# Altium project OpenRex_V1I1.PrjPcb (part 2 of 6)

## Sheet [10] - CPU - GPIO, PWM, LEDS, BUTTONS.SchDoc
size A2; DocumentNumber: 10; SheetNumber: 10; SheetTotal: 31
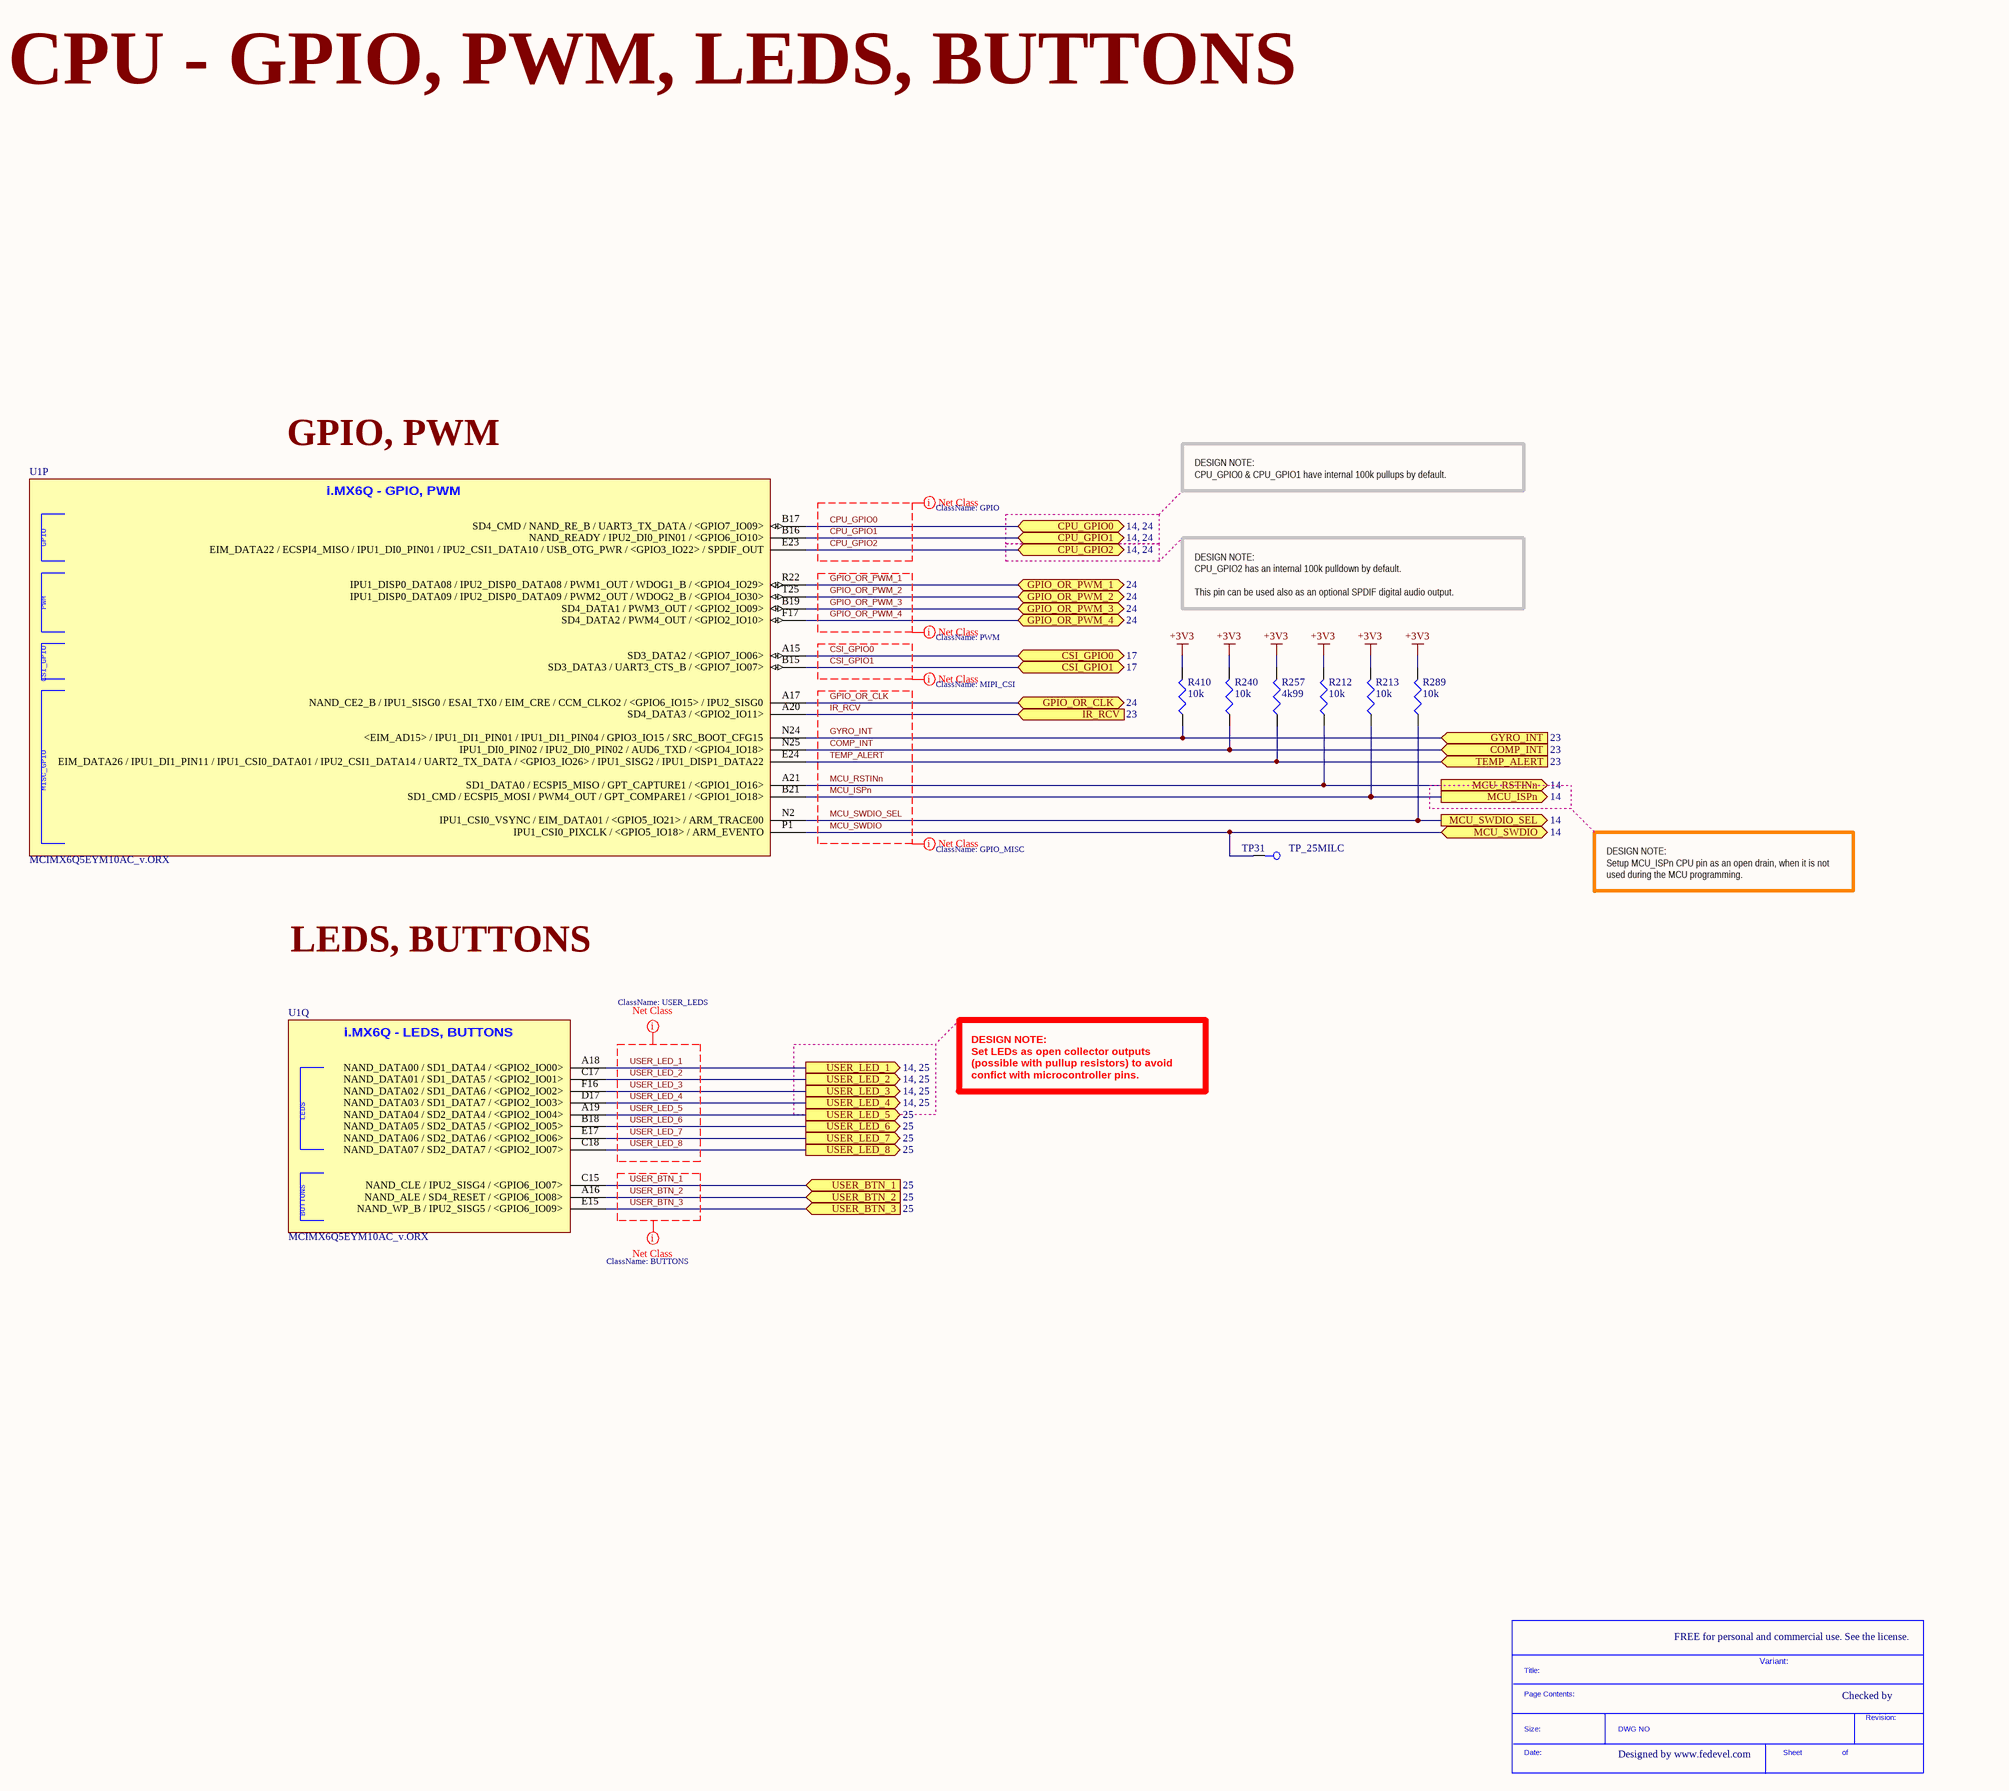
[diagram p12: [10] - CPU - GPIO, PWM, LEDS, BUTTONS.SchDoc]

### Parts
(Parts that share a designator on the sheet are numbered #1, #2 ... from top to bottom, then left to right.)
*#9  SDTitleBlock  (value not drawn)  (graphical)
R212  10k  [R0402]
R213  10k  [R0402]
R240  10k  [R0402]
R257  4k99  [R0402]
R289  10k  [R0402]
R410  10k  [R0402]
TP31  TP_25MILC  [TP_25C]  (no BOM)
U1  MCIMX6Q5EYM10AC_v.ORX  [PBGA624]  (parts P,Q of 21)

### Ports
COMP_INT (in, see 23), CPU_GPIO0 (bidir, see 14, 24), CPU_GPIO1 (bidir, see 14, 24), CPU_GPIO2 (bidir, see 14, 24), CSI_GPIO0 (bidir, see 17), CSI_GPIO1 (bidir, see 17), GPIO_OR_CLK (bidir, see 24), GPIO_OR_PWM_1 (bidir, see 24), GPIO_OR_PWM_2 (bidir, see 24), GPIO_OR_PWM_3 (bidir, see 24), GPIO_OR_PWM_4 (bidir, see 24), GYRO_INT (in, see 23), IR_RCV (in, see 23), MCU_ISPn (out, see 14), MCU_RSTINn (out, see 14), MCU_SWDIO (bidir, see 14), MCU_SWDIO_SEL (out, see 14), TEMP_ALERT (in, see 23), USER_BTN_1 (in, see 25), USER_BTN_2 (in, see 25), USER_BTN_3 (in, see 25), USER_LED_1 (out, see 14, 25), USER_LED_2 (out, see 14, 25), USER_LED_3 (out, see 14, 25), USER_LED_4 (out, see 14, 25), USER_LED_5 (out, see 25), USER_LED_6 (out, see 25), USER_LED_7 (out, see 25), USER_LED_8 (out, see 25)

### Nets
+3V3: R212.2 R213.2 R240.2 R257.2 R289.2 R410.2
COMP_INT: R240.1 U1.N25(IPU1_DI0_PIN02_/_IPU2_DI0_PIN02_/_AUD6_TXD_/_<GPIO4_IO18>) ; port COMP_INT
CPU_GPIO0: U1.B17(SD4_CMD_/_NAND_RE_B_/_UART3_TX_DATA_/_<GPIO7_IO09>) ; port CPU_GPIO0
CPU_GPIO1: U1.B16(NAND_READY_/_IPU2_DI0_PIN01_/_<GPIO6_IO10>) ; port CPU_GPIO1
CPU_GPIO2: U1.E23(EIM_DATA22_/_ECSPI4_MISO_/_IPU1_DI0_PIN01_/_IPU2_CSI1_DATA10_/_USB_OTG_PWR_/_<GPIO3_IO22>_/_SPDIF_OUT) ; port CPU_GPIO2
CSI_GPIO0: U1.A15(SD3_DATA2_/_<GPIO7_IO06>) ; port CSI_GPIO0
CSI_GPIO1: U1.B15(SD3_DATA3_/_UART3_CTS_B_/_<GPIO7_IO07>) ; port CSI_GPIO1
GPIO_OR_CLK: U1.A17(NAND_CE2_B_/_IPU1_SISG0_/_ESAI_TX0_/_EIM_CRE_/_CCM_CLKO2_/_<GPIO6_IO15>_/_IPU2_SISG0) ; port GPIO_OR_CLK
GPIO_OR_PWM_1: U1.R22(IPU1_DISP0_DATA08_/_IPU2_DISP0_DATA08_/_PWM1_OUT_/_WDOG1_B_/_<GPIO4_IO29>) ; port GPIO_OR_PWM_1
GPIO_OR_PWM_2: U1.T25(IPU1_DISP0_DATA09_/_IPU2_DISP0_DATA09_/_PWM2_OUT_/_WDOG2_B_/_<GPIO4_IO30>) ; port GPIO_OR_PWM_2
GPIO_OR_PWM_3: U1.B19(SD4_DATA1_/_PWM3_OUT_/_<GPIO2_IO09>) ; port GPIO_OR_PWM_3
GPIO_OR_PWM_4: U1.F17(SD4_DATA2_/_PWM4_OUT_/_<GPIO2_IO10>) ; port GPIO_OR_PWM_4
GYRO_INT: R410.1 U1.N24(<EIM_AD15>_/_IPU1_DI1_PIN01_/_IPU1_DI1_PIN04_/_GPIO3_IO15_/_SRC_BOOT_CFG15) ; port GYRO_INT
IR_RCV: U1.A20(SD4_DATA3_/_<GPIO2_IO11>) ; port IR_RCV
MCU_ISPn: R213.1 U1.B21(SD1_CMD_/_ECSPI5_MOSI_/_PWM4_OUT_/_GPT_COMPARE1_/_<GPIO1_IO18>) ; port MCU_ISPn
MCU_RSTINn: R212.1 U1.A21(SD1_DATA0_/_ECSPI5_MISO_/_GPT_CAPTURE1_/_<GPIO1_IO16>) ; port MCU_RSTINn
MCU_SWDIO: TP31.1 U1.P1(IPU1_CSI0_PIXCLK_/_<GPIO5_IO18>_/_ARM_EVENTO) ; port MCU_SWDIO
MCU_SWDIO_SEL: R289.1 U1.N2(IPU1_CSI0_VSYNC_/_EIM_DATA01_/_<GPIO5_IO21>_/_ARM_TRACE00) ; port MCU_SWDIO_SEL
TEMP_ALERT: R257.1 U1.E24(EIM_DATA26_/_IPU1_DI1_PIN11_/_IPU1_CSI0_DATA01_/_IPU2_CSI1_DATA14_/_UART2_TX_DATA_/_<GPIO3_IO26>_/_IPU1_SISG2_/_IPU1_DISP1_DATA22) ; port TEMP_ALERT
USER_BTN_1: U1.C15(NAND_CLE_/_IPU2_SISG4_/_<GPIO6_IO07>) ; port USER_BTN_1
USER_BTN_2: U1.A16(NAND_ALE_/_SD4_RESET_/_<GPIO6_IO08>) ; port USER_BTN_2
USER_BTN_3: U1.E15(NAND_WP_B_/_IPU2_SISG5_/_<GPIO6_IO09>) ; port USER_BTN_3
USER_LED_1: U1.A18(NAND_DATA00_/_SD1_DATA4_/_<GPIO2_IO00>) ; port USER_LED_1
USER_LED_2: U1.C17(NAND_DATA01_/_SD1_DATA5_/_<GPIO2_IO01>) ; port USER_LED_2
USER_LED_3: U1.F16(NAND_DATA02_/_SD1_DATA6_/_<GPIO2_IO02>) ; port USER_LED_3
USER_LED_4: U1.D17(NAND_DATA03_/_SD1_DATA7_/_<GPIO2_IO03>) ; port USER_LED_4
USER_LED_5: U1.A19(NAND_DATA04_/_SD2_DATA4_/_<GPIO2_IO04>) ; port USER_LED_5
USER_LED_6: U1.B18(NAND_DATA05_/_SD2_DATA5_/_<GPIO2_IO05>) ; port USER_LED_6
USER_LED_7: U1.E17(NAND_DATA06_/_SD2_DATA6_/_<GPIO2_IO06>) ; port USER_LED_7
USER_LED_8: U1.C18(NAND_DATA07_/_SD2_DATA7_/_<GPIO2_IO07>) ; port USER_LED_8

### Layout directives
net class PWM: GPIO_OR_PWM_1, GPIO_OR_PWM_2, GPIO_OR_PWM_3, GPIO_OR_PWM_4
net class GPIO: CPU_GPIO0, CPU_GPIO1, CPU_GPIO2
net class GPIO_MISC: COMP_INT, GPIO_OR_CLK, GYRO_INT, IR_RCV, MCU_ISPn, MCU_RSTINn, MCU_SWDIO, MCU_SWDIO_SEL, TEMP_ALERT
net class USER_LEDS: USER_LED_1, USER_LED_2, USER_LED_3, USER_LED_4, USER_LED_5, USER_LED_6, USER_LED_7, USER_LED_8
net class BUTTONS: USER_BTN_1, USER_BTN_2, USER_BTN_3
net class MIPI_CSI: CSI_GPIO0, CSI_GPIO1

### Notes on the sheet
- CPU - GPIO, PWM, LEDS, BUTTONS
- GPIO, PWM
- DESIGN NOTE:
  CPU_GPIO0 & CPU_GPIO1 have internal 100k pullups by default.
- DESIGN NOTE:
  CPU_GPIO2 has an internal 100k pulldown by default.
  This pin can be used also as an optional SPDIF digital audio output.
- DESIGN NOTE:
  Setup MCU_ISPn CPU pin as an open drain, when it is not used during the MCU programming.
- LEDS, BUTTONS
- DESIGN NOTE:
  Set LEDs as open collector outputs (possible with pullup resistors) to avoid confict with microcontroller pins.
- FREE for personal and commercial use. See the license.
- Variant:
- Checked by
- Designed by www.fedevel.com

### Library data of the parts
R212 R213 R240 R289 R410 = RC0402FR-0710KL: RES 10.0K OHM 1/16W 1% 0402 SMD; Manufacturer: Yageo; Power (Watts): 0.063W, 1/16W; .Checked PCB: used; Temperature Coefficient: ±100ppm/°C
R257 = RMCF0402FT4K99: RES TF 4.99K OHM 1% 1/16W 0402; Manufacturer: Stackpole Electronics Inc; Power (Watts): 0.063W, 1/16W; .Checked PCB: used; Temperature Coefficient: ±100ppm/°C
TP31 = TP_25MILC: Test Point 25mil
U1 = MCIMX6Q5EYM10AC_v.ORX: IC MCU 32BIT ARM QUAD 624FCBGA; Manufacturer: Freescale Semiconductor; Core Processor: ARM® Cortex™-A9; Core Size: 32-Bit Quad-Core; Speed: 1.0GHz; Connectivity: CAN, EBI/EMI, ESAI, Ethernet, GPMI, I2C, MMC/SD, PCI, SATA, SPI, UART, USB, USB OTG; Peripherals: DMA, HDMI, I2S/SSI/AC97, MIPI CSI, MIMI DSI, MIPI HIS, PWM, WDT; Number of I /O: 224; Program Memory Type: External Program Memory; RAM Size: 256K x 8; Voltage - Supply (Vcc/Vdd): 0.925 V ~ 1.5 V; Oscillator Type: Internal; .Creator: MM; .Checked PCB: MM, checked by RF

## Sheet [09] - CPU - SD, AUDIO, I2C, CAN.SchDoc
size A2; DocumentNumber: 9; SheetNumber: 9; SheetTotal: 31
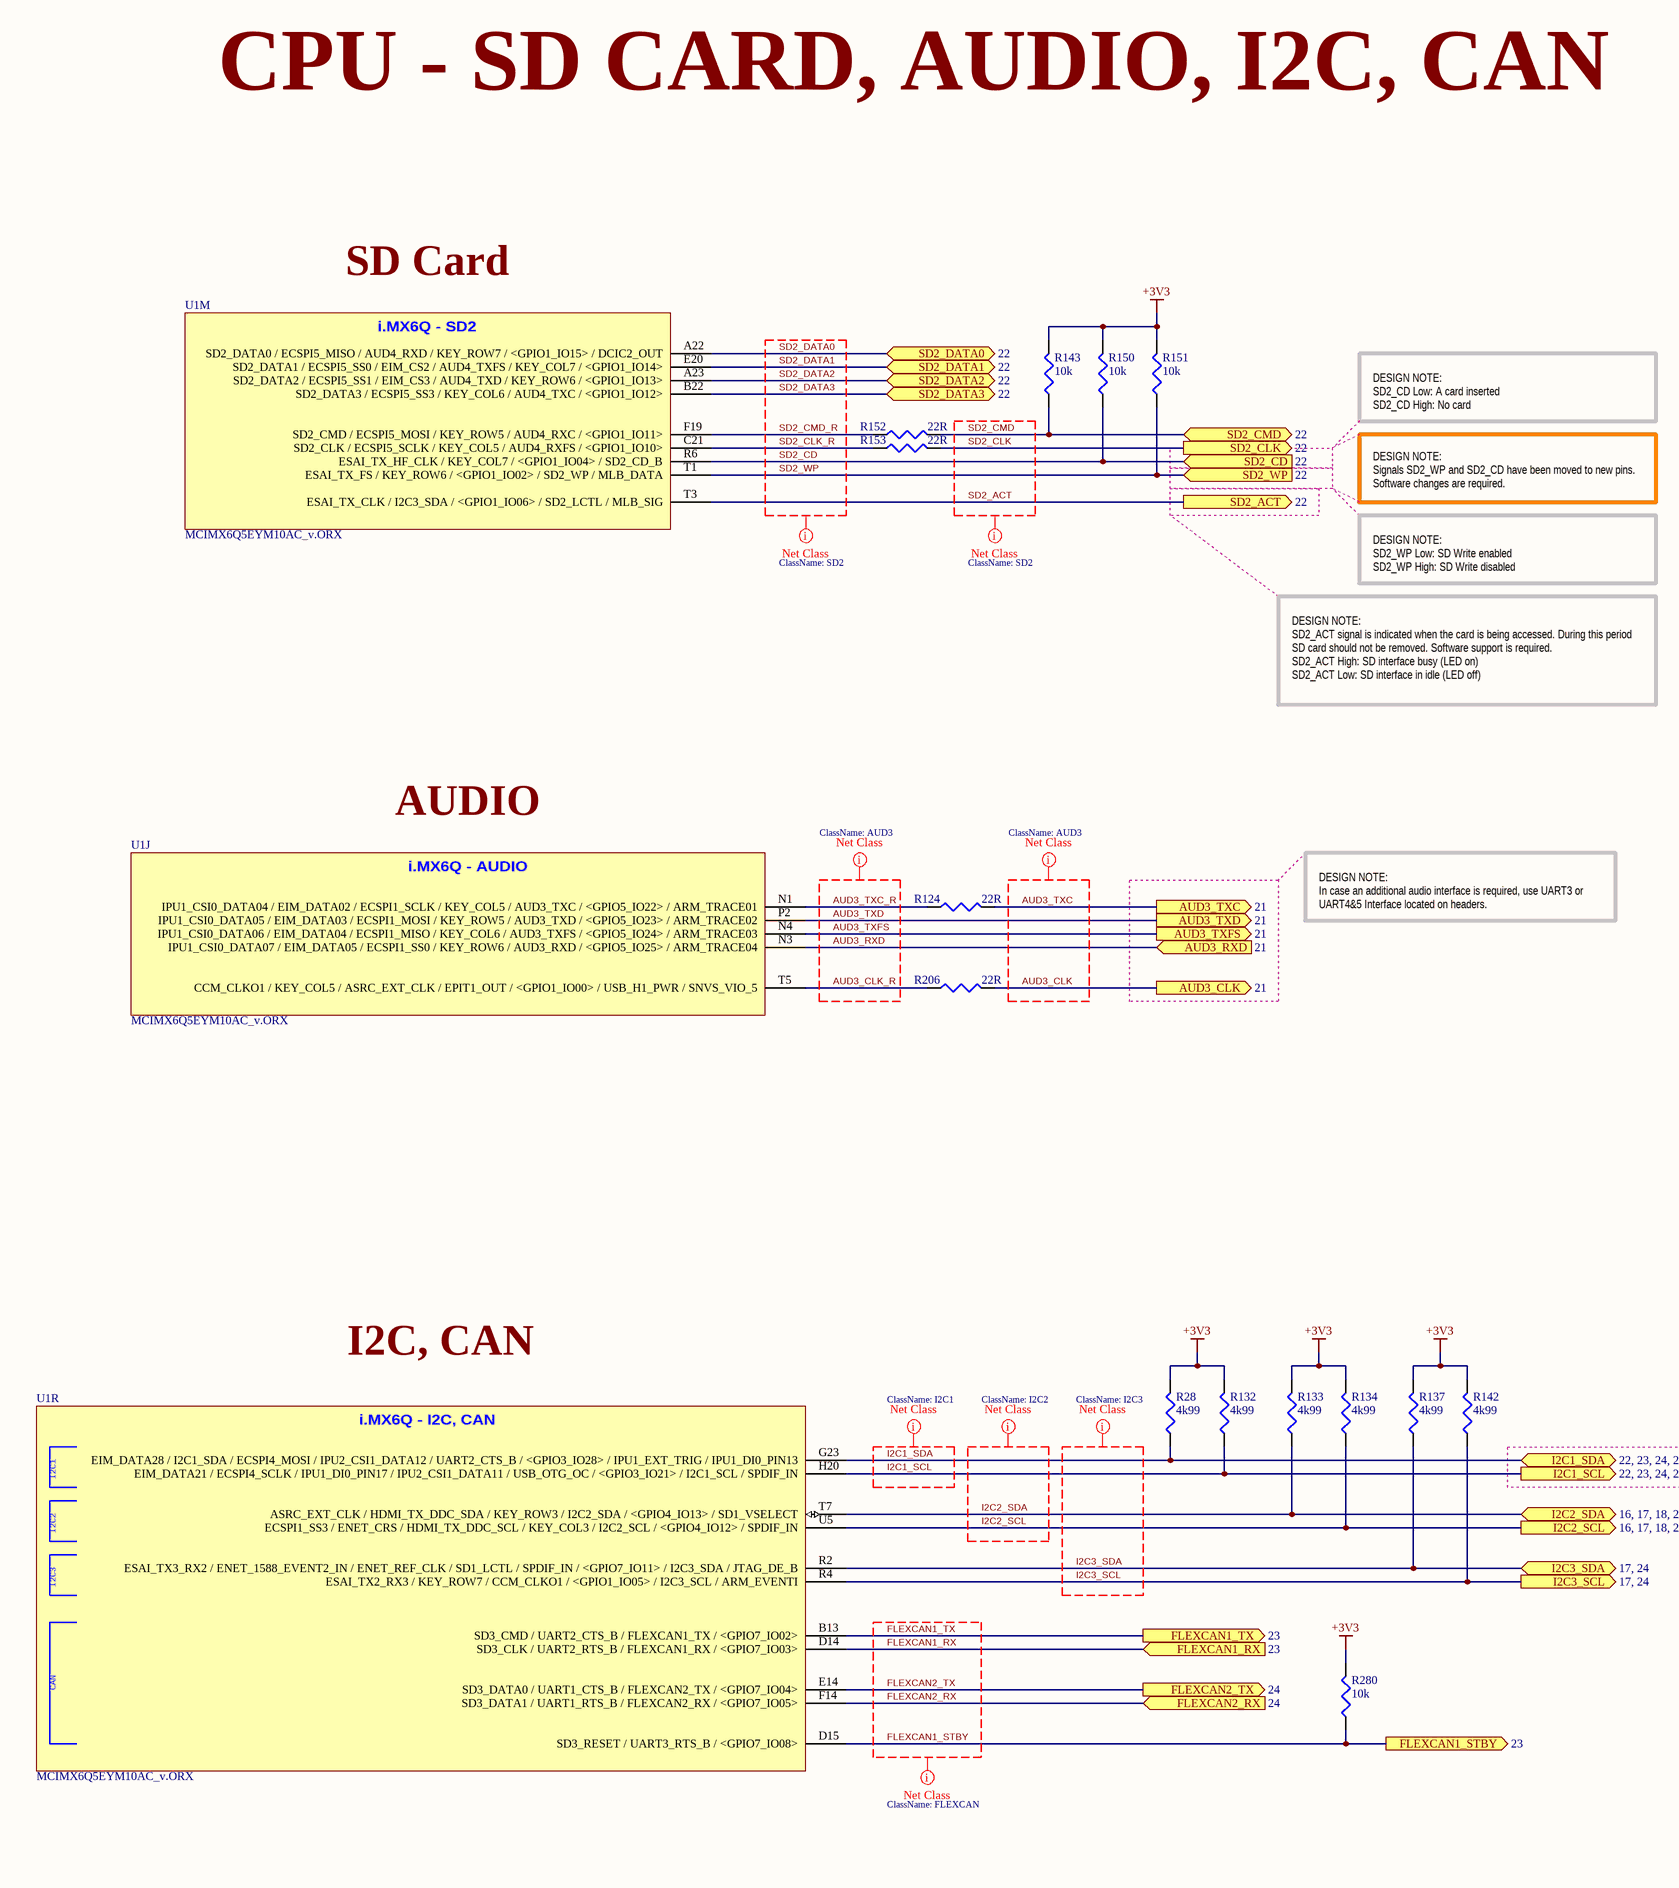
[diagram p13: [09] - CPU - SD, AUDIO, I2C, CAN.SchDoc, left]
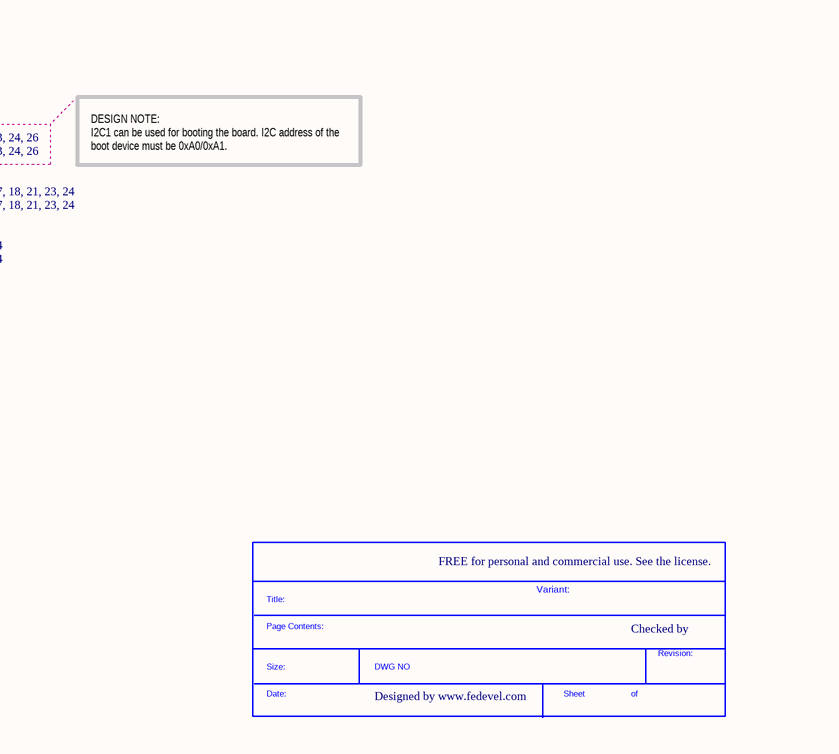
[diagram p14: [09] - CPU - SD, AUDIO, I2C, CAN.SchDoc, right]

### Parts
(Parts that share a designator on the sheet are numbered #1, #2 ... from top to bottom, then left to right.)
*#10  SDTitleBlock  (value not drawn)  (graphical)
R28  4k99  [R0402]
R124  22R  [R0402]
R132  4k99  [R0402]
R133  4k99  [R0402]
R134  4k99  [R0402]
R137  4k99  [R0402]
R142  4k99  [R0402]
R143  10k  [R0402]
R150  10k  [R0402]
R151  10k  [R0402]
R152  22R  [R0402]
R153  22R  [R0402]
R206  22R  [R0402]
R280  10k  [R0402]
U1  MCIMX6Q5EYM10AC_v.ORX  [PBGA624]  (parts J,M,R of 21)

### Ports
AUD3_CLK (out, see 21), AUD3_RXD (in, see 21), AUD3_TXC (out, see 21), AUD3_TXD (out, see 21), AUD3_TXFS (out, see 21), FLEXCAN1_RX (in, see 23), FLEXCAN1_STBY (out, see 23), FLEXCAN1_TX (out, see 23), FLEXCAN2_RX (in, see 24), FLEXCAN2_TX (out, see 24), I2C1_SCL (see 22, 23, 24, 26), I2C1_SDA (bidir, see 22, 23, 24, 26), I2C2_SCL (see 16, 17, 18, 21, 23, 24), I2C2_SDA (bidir, see 16, 17, 18, 21, 23, 24), I2C3_SCL (see 17, 24), I2C3_SDA (bidir, see 17, 24), SD2_ACT (out, see 22), SD2_CD (in, see 22), SD2_CLK (out, see 22), SD2_CMD (bidir, see 22), SD2_DATA0 (bidir, see 22), SD2_DATA1 (bidir, see 22), SD2_DATA2 (bidir, see 22), SD2_DATA3 (bidir, see 22), SD2_WP (in, see 22)

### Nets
+3V3: R28.2 R132.2 R133.2 R134.2 R137.2 R142.2 R143.2 R150.2 R151.2 R280.2
AUD3_CLK: R206.2 ; port AUD3_CLK
AUD3_CLK_R: R206.1 U1.T5(CCM_CLKO1_/_KEY_COL5_/_ASRC_EXT_CLK_/_EPIT1_OUT_/_<GPIO1_IO00>_/_USB_H1_PWR_/_SNVS_VIO_5)
AUD3_RXD: U1.N3(IPU1_CSI0_DATA07_/_EIM_DATA05_/_ECSPI1_SS0_/_KEY_ROW6_/_AUD3_RXD_/_<GPIO5_IO25>_/_ARM_TRACE04) ; port AUD3_RXD
AUD3_TXC: R124.2 ; port AUD3_TXC
AUD3_TXC_R: R124.1 U1.N1(IPU1_CSI0_DATA04_/_EIM_DATA02_/_ECSPI1_SCLK_/_KEY_COL5_/_AUD3_TXC_/_<GPIO5_IO22>_/_ARM_TRACE01)
AUD3_TXD: U1.P2(IPU1_CSI0_DATA05_/_EIM_DATA03_/_ECSPI1_MOSI_/_KEY_ROW5_/_AUD3_TXD_/_<GPIO5_IO23>_/_ARM_TRACE02) ; port AUD3_TXD
AUD3_TXFS: U1.N4(IPU1_CSI0_DATA06_/_EIM_DATA04_/_ECSPI1_MISO_/_KEY_COL6_/_AUD3_TXFS_/_<GPIO5_IO24>_/_ARM_TRACE03) ; port AUD3_TXFS
FLEXCAN1_RX: U1.D14(SD3_CLK_/_UART2_RTS_B_/_FLEXCAN1_RX_/_<GPIO7_IO03>) ; port FLEXCAN1_RX
FLEXCAN1_STBY: R280.1 U1.D15(SD3_RESET_/_UART3_RTS_B_/_<GPIO7_IO08>) ; port FLEXCAN1_STBY
FLEXCAN1_TX: U1.B13(SD3_CMD_/_UART2_CTS_B_/_FLEXCAN1_TX_/_<GPIO7_IO02>) ; port FLEXCAN1_TX
FLEXCAN2_RX: U1.F14(SD3_DATA1_/_UART1_RTS_B_/_FLEXCAN2_RX_/_<GPIO7_IO05>) ; port FLEXCAN2_RX
FLEXCAN2_TX: U1.E14(SD3_DATA0_/_UART1_CTS_B_/_FLEXCAN2_TX_/_<GPIO7_IO04>) ; port FLEXCAN2_TX
I2C1_SCL: R132.1 U1.H20(EIM_DATA21_/_ECSPI4_SCLK_/_IPU1_DI0_PIN17_/_IPU2_CSI1_DATA11_/_USB_OTG_OC_/_<GPIO3_IO21>_/_I2C1_SCL_/_SPDIF_IN) ; port I2C1_SCL
I2C1_SDA: R28.1 U1.G23(EIM_DATA28_/_I2C1_SDA_/_ECSPI4_MOSI_/_IPU2_CSI1_DATA12_/_UART2_CTS_B_/_<GPIO3_IO28>_/_IPU1_EXT_TRIG_/_IPU1_DI0_PIN13) ; port I2C1_SDA
I2C2_SCL: R134.1 U1.U5(ECSPI1_SS3_/_ENET_CRS_/_HDMI_TX_DDC_SCL_/_KEY_COL3_/_I2C2_SCL_/_<GPIO4_IO12>_/_SPDIF_IN) ; port I2C2_SCL
I2C2_SDA: R133.1 U1.T7(ASRC_EXT_CLK_/_HDMI_TX_DDC_SDA_/_KEY_ROW3_/_I2C2_SDA_/_<GPIO4_IO13>_/_SD1_VSELECT) ; port I2C2_SDA
I2C3_SCL: R142.1 U1.R4(ESAI_TX2_RX3_/_KEY_ROW7_/_CCM_CLKO1_/_<GPIO1_IO05>_/_I2C3_SCL_/_ARM_EVENTI) ; port I2C3_SCL
I2C3_SDA: R137.1 U1.R2(ESAI_TX3_RX2_/_ENET_1588_EVENT2_IN_/_ENET_REF_CLK_/_SD1_LCTL_/_SPDIF_IN_/_<GPIO7_IO11>_/_I2C3_SDA_/_JTAG_DE_B) ; port I2C3_SDA
SD2_ACT: U1.T3(ESAI_TX_CLK_/_I2C3_SDA_/_<GPIO1_IO06>_/_SD2_LCTL_/_MLB_SIG) ; port SD2_ACT
SD2_CD: R150.1 U1.R6(ESAI_TX_HF_CLK_/_KEY_COL7_/_<GPIO1_IO04>_/_SD2_CD_B) ; port SD2_CD
SD2_CLK: R153.2 ; port SD2_CLK
SD2_CLK_R: R153.1 U1.C21(SD2_CLK_/_ECSPI5_SCLK_/_KEY_COL5_/_AUD4_RXFS_/_<GPIO1_IO10>)
SD2_CMD: R143.1 R152.2 ; port SD2_CMD
SD2_CMD_R: R152.1 U1.F19(SD2_CMD_/_ECSPI5_MOSI_/_KEY_ROW5_/_AUD4_RXC_/_<GPIO1_IO11>)
SD2_DATA0: U1.A22(SD2_DATA0_/_ECSPI5_MISO_/_AUD4_RXD_/_KEY_ROW7_/_<GPIO1_IO15>_/_DCIC2_OUT) ; port SD2_DATA0
SD2_DATA1: U1.E20(SD2_DATA1_/_ECSPI5_SS0_/_EIM_CS2_/_AUD4_TXFS_/_KEY_COL7_/_<GPIO1_IO14>) ; port SD2_DATA1
SD2_DATA2: U1.A23(SD2_DATA2_/_ECSPI5_SS1_/_EIM_CS3_/_AUD4_TXD_/_KEY_ROW6_/_<GPIO1_IO13>) ; port SD2_DATA2
SD2_DATA3: U1.B22(SD2_DATA3_/_ECSPI5_SS3_/_KEY_COL6_/_AUD4_TXC_/_<GPIO1_IO12>) ; port SD2_DATA3
SD2_WP: R151.1 U1.T1(ESAI_TX_FS_/_KEY_ROW6_/_<GPIO1_IO02>_/_SD2_WP_/_MLB_DATA) ; port SD2_WP

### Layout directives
net class AUD3: AUD3_CLK, AUD3_CLK_R, AUD3_RXD, AUD3_TXC, AUD3_TXC_R, AUD3_TXD, AUD3_TXFS
net class FLEXCAN: FLEXCAN1_RX, FLEXCAN1_STBY, FLEXCAN1_TX, FLEXCAN2_RX, FLEXCAN2_TX
net class I2C1: I2C1_SCL, I2C1_SDA
net class I2C2: I2C2_SCL, I2C2_SDA
net class I2C3: I2C3_SCL, I2C3_SDA
net class SD2: SD2_ACT, SD2_CD, SD2_CLK, SD2_CLK_R, SD2_CMD, SD2_CMD_R, SD2_DATA0, SD2_DATA1, SD2_DATA2, SD2_DATA3, SD2_WP

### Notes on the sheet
- CPU - SD CARD, AUDIO, I2C, CAN
- SD Card
- DESIGN NOTE:
  SD2_CD Low: A card inserted
  SD2_CD High: No card
- DESIGN NOTE:
  Signals SD2_WP and SD2_CD have been moved to new pins. Software changes are required.
- DESIGN NOTE:
  SD2_WP Low: SD Write enabled
  SD2_WP High: SD Write disabled
- DESIGN NOTE:
  SD2_ACT signal is indicated when the card is being accessed. During this period SD card should not be removed. Software support is required.
  SD2_ACT High: SD interface busy (LED on)
  SD2_ACT Low: SD interface in idle (LED off)
- AUDIO
- DESIGN NOTE:
  In case an additional audio interface is required, use UART3 or UART4&5 Interface located on headers.
- I2C, CAN
- DESIGN NOTE:
  I2C1 can be used for booting the board. I2C address of the boot device must be 0xA0/0xA1.
- FREE for personal and commercial use. See the license.
- Variant:
- Checked by
- Designed by www.fedevel.com

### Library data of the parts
R28 R132-R134 R137 R142 = RMCF0402FT4K99: as R257 on sheet [10] - CPU - GPIO, PWM, LEDS, BUTTONS
R124 R152 R153 R206 = RC0402FR-0722RL: RES 22.0 OHM 1/16W 1% 0402 SMD; Manufacturer: Yageo; Resistance (Ohms): 22; Power (Watts): 0.063W, 1/16W; .Checked PCB: used; Temperature Coefficient: ±100ppm/°C
R143 R150 R151 R280 = RC0402FR-0710KL: as R212 on sheet [10] - CPU - GPIO, PWM, LEDS, BUTTONS
U1 = MCIMX6Q5EYM10AC_v.ORX: as U1 on sheet [10] - CPU - GPIO, PWM, LEDS, BUTTONS

## Sheet [03] - CPU - DDR3, DDR3 MEM.SchDoc
size A2; DocumentNumber: 3; SheetNumber: 3; SheetTotal: 31
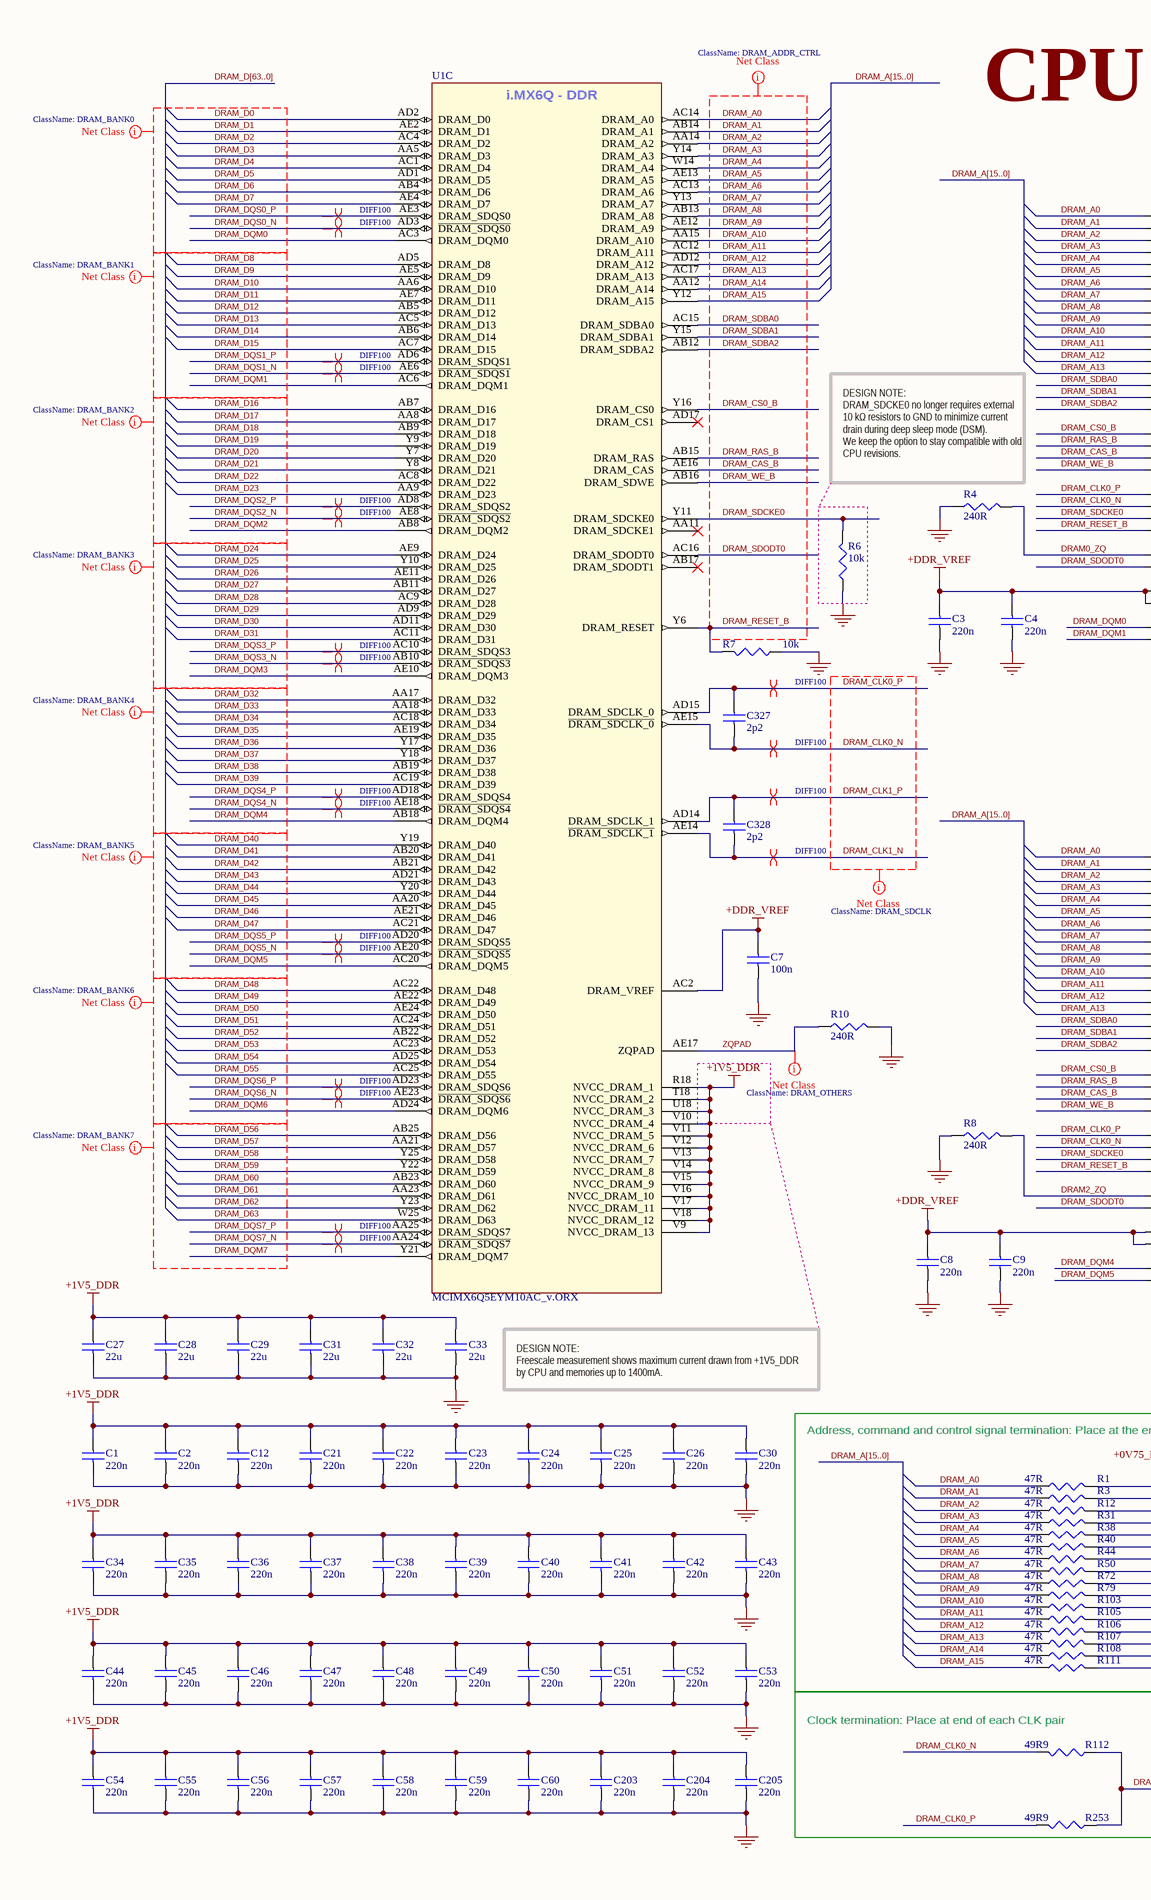
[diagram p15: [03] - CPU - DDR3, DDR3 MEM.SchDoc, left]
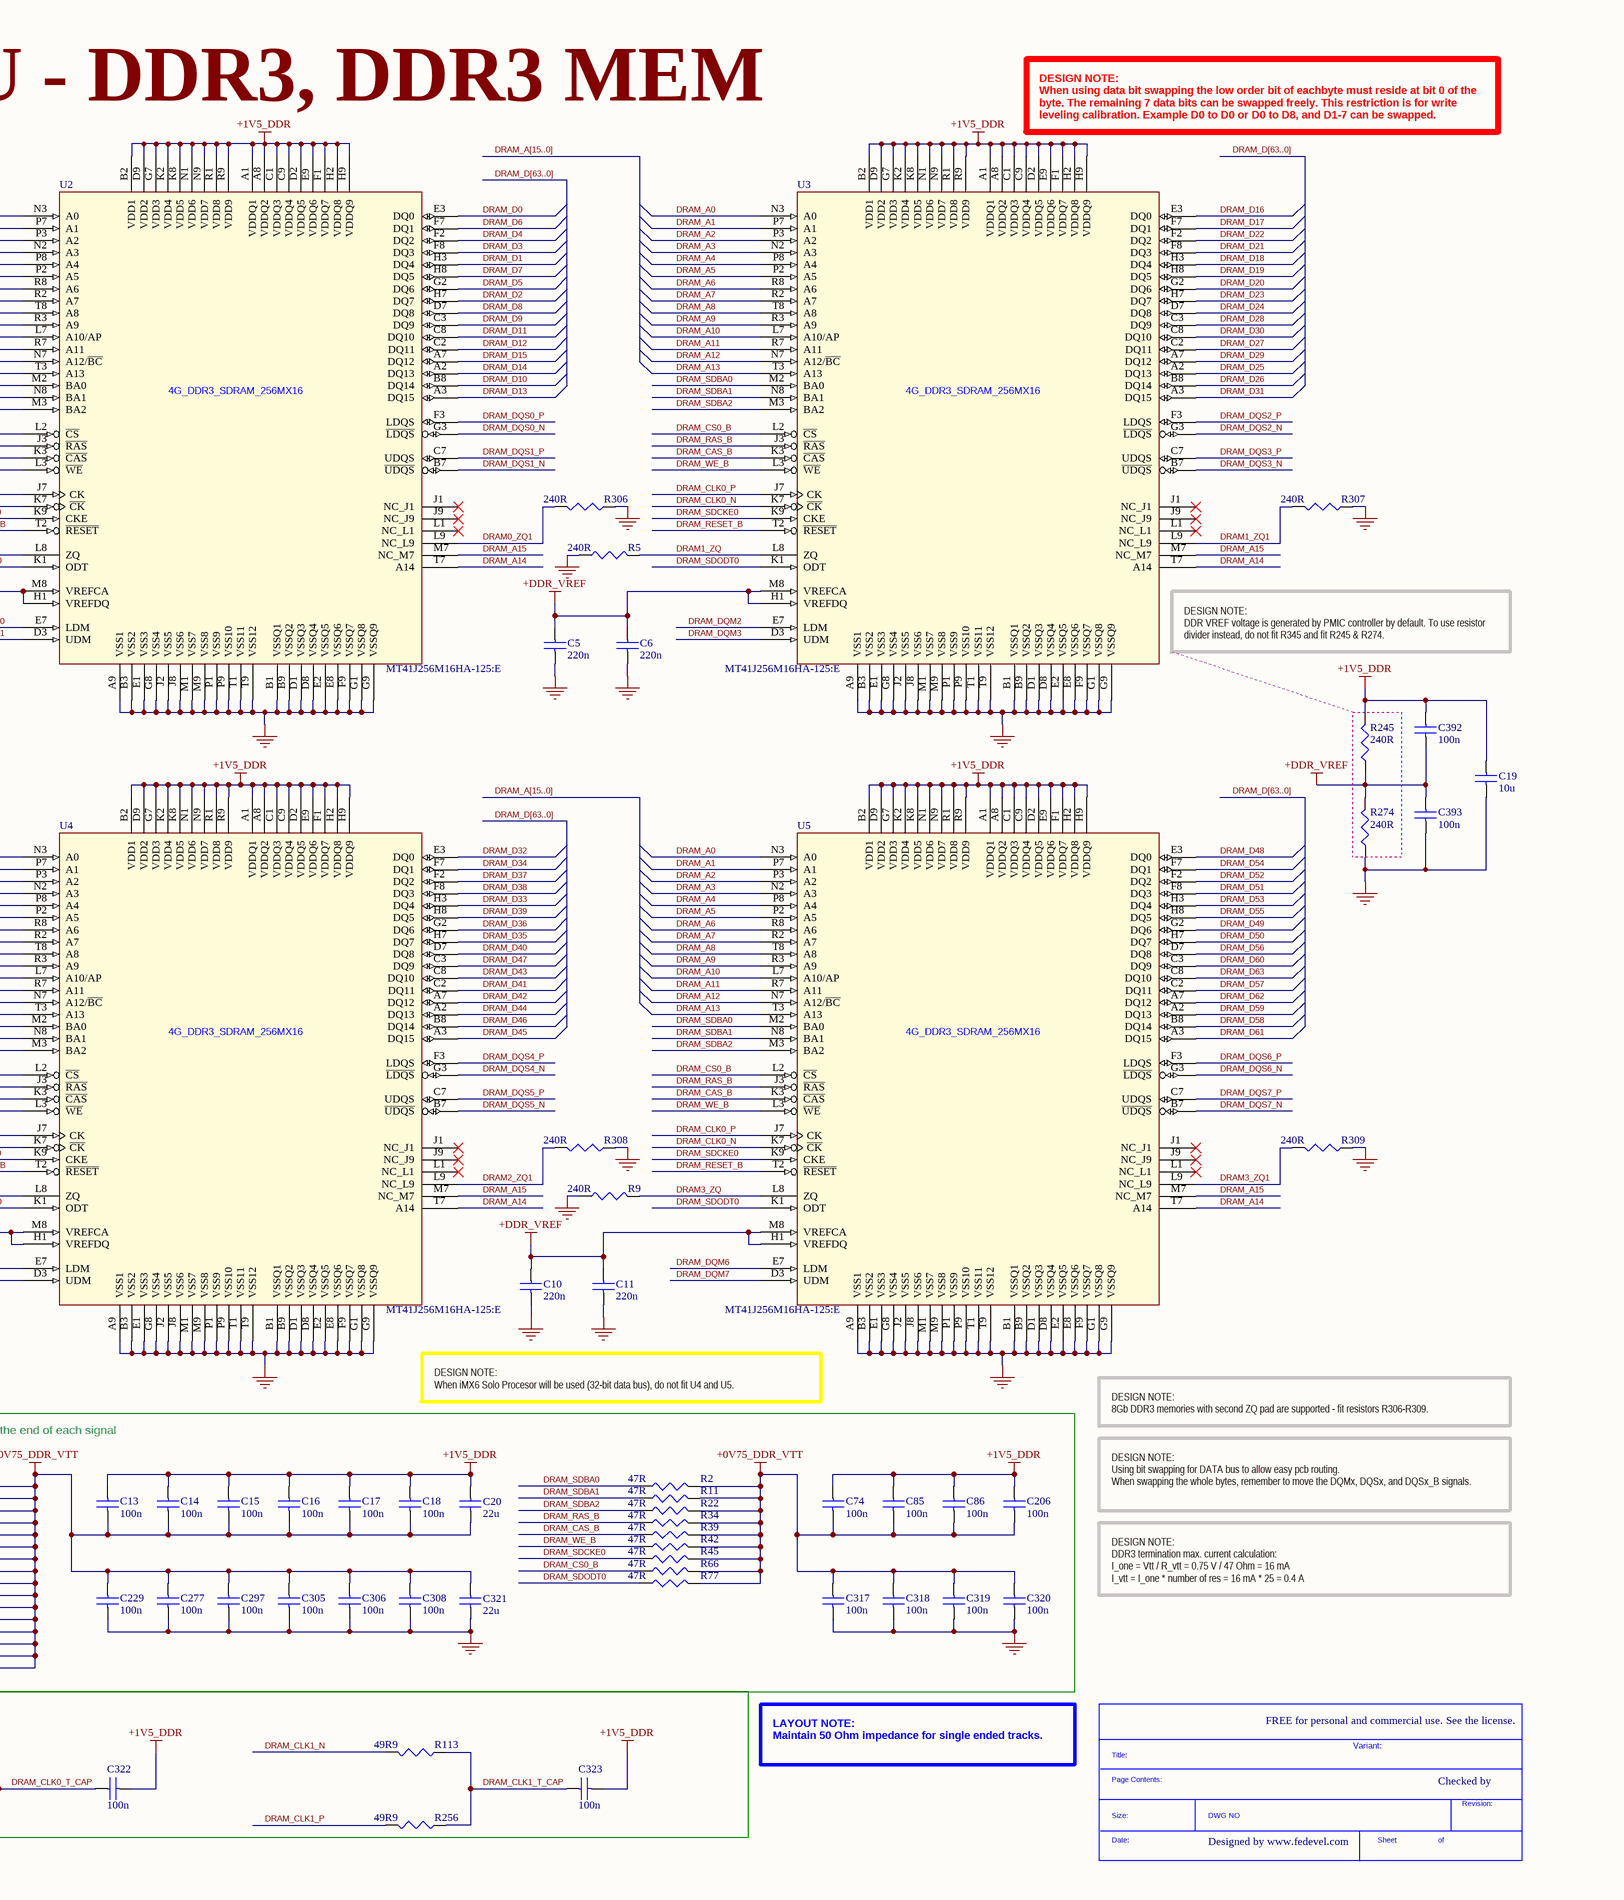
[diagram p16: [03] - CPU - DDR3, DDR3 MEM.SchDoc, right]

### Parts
(Parts that share a designator on the sheet are numbered #1, #2 ... from top to bottom, then left to right.)
*#11  SDTitleBlock  (value not drawn)  (graphical)
C1  220n  [C0201]
C2  220n  [C0201]
C3  220n  [C0201]
C4  220n  [C0201]
C5  220n  [C0201]
C6  220n  [C0201]
C7  100n  [C0201]
C8  220n  [C0201]
C9  220n  [C0201]
C10  220n  [C0201]
C11  220n  [C0201]
C12  220n  [C0201]
C13  100n  [C0201]
C14  100n  [C0201]
C15  100n  [C0201]
C16  100n  [C0201]
C17  100n  [C0201]
C18  100n  [C0201]
C19  10u  [C0603]
C20  22u  [C0603]
C21  220n  [C0201]
C22  220n  [C0201]
C23  220n  [C0201]
C24  220n  [C0201]
C25  220n  [C0201]
C26  220n  [C0201]
C27  22u  [C0603]
C28  22u  [C0603]
C29  22u  [C0603]
C30  220n  [C0201]
C31  22u  [C0603]
C32  22u  [C0603]
C33  22u  [C0603]
C34  220n  [C0201]
C35  220n  [C0201]
C36  220n  [C0201]
C37  220n  [C0201]
C38  220n  [C0201]
C39  220n  [C0201]
C40  220n  [C0201]
C41  220n  [C0201]
C42  220n  [C0201]
C43  220n  [C0201]
C44  220n  [C0201]
C45  220n  [C0201]
C46  220n  [C0201]
C47  220n  [C0201]
C48  220n  [C0201]
C49  220n  [C0201]
C50  220n  [C0201]
C51  220n  [C0201]
C52  220n  [C0201]
C53  220n  [C0201]
C54  220n  [C0201]
C55  220n  [C0201]
C56  220n  [C0201]
C57  220n  [C0201]
C58  220n  [C0201]
C59  220n  [C0201]
C60  220n  [C0201]
C74  100n  [C0201]
C85  100n  [C0201]
C86  100n  [C0201]
C203  220n  [C0201]
C204  220n  [C0201]
C205  220n  [C0201]
C206  100n  [C0201]
C229  100n  [C0201]
C277  100n  [C0201]
C297  100n  [C0201]
C305  100n  [C0201]
C306  100n  [C0201]
C308  100n  [C0201]
C317  100n  [C0201]
C318  100n  [C0201]
C319  100n  [C0201]
C320  100n  [C0201]
C321  22u  [C0603]
C322  100n  [C0201]
C323  100n  [C0201]
C327  2p2  [C0201]
C328  2p2  [C0201]
C392  100n  [C0402]
C393  100n  [C0402]
R1  47R  [R0201]
R2  47R  [R0201]
R3  47R  [R0201]
R4  240R  [R0201]
R5  240R  [R0201]
R6  10k  [R0201]
R7  10k  [R0201]
R8  240R  [R0201]
R9  240R  [R0201]
R10  240R  [R0201]
R11  47R  [R0201]
R12  47R  [R0201]
R22  47R  [R0201]
R31  47R  [R0201]
R34  47R  [R0201]
R38  47R  [R0201]
R39  47R  [R0201]
R40  47R  [R0201]
R42  47R  [R0201]
R44  47R  [R0201]
R45  47R  [R0201]
R50  47R  [R0201]
R66  47R  [R0201]
R72  47R  [R0201]
R77  47R  [R0201]
R79  47R  [R0201]
R103  47R  [R0201]
R105  47R  [R0201]
R106  47R  [R0201]
R107  47R  [R0201]
R108  47R  [R0201]
R111  47R  [R0201]
R112  49R9  [R0201]
R113  49R9  [R0201]
R245  240R  [R0402]
R253  49R9  [R0201]
R256  49R9  [R0201]
R274  240R  [R0402]
R306  240R  [R0201]
R307  240R  [R0201]
R308  240R  [R0201]
R309  240R  [R0201]
U1  MCIMX6Q5EYM10AC_v.ORX  [PBGA624]  (part C of 21)
U2  MT41J256M16HA-125:E  [96_FPGA_DD3_14mmx10mm-small_size]
U3  MT41J256M16HA-125:E  [96_FPGA_DD3_14mmx10mm-small_size]
U4  MT41J256M16HA-125:E  [96_FPGA_DD3_14mmx10mm-small_size]
U5  MT41J256M16HA-125:E  [96_FPGA_DD3_14mmx10mm-small_size]

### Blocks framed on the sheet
Clock termination: Place at end of each CLK pair: C322 C323 R112 R113 R253 R256

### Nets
+0V75_DDR_VTT: C13.2 C14.2 C15.2 C16.2 C17.2 C18.2 C20.2 C74.2 C85.2 C86.2 C206.2 C229.1 C277.1 C297.1 C305.1 C306.1 C308.1 C317.1 C318.1 C319.1 C320.1 C321.1 R1.2 R2.2 R3.2 R11.2 R12.2 R22.2 R31.2 R34.2 R38.2 R39.2 R40.2 R42.2 R44.2 R45.2 R50.2 R66.2 R72.2 R77.2 R79.2 R103.2 R105.2 R106.2 R107.2 R108.2 R111.2
+1V5_DDR: C1.1 C2.1 C12.1 C13.1 C14.1 C15.1 C16.1 C17.1 C18.1 C19.1 C20.1 C21.1 C22.1 C23.1 C24.1 C25.1 C26.1 C27.1 C28.1 C29.1 C30.1 C31.1 C32.1 C33.1 C34.1 C35.1 C36.1 C37.1 C38.1 C39.1 C40.1 C41.1 C42.1 C43.1 C44.1 C45.1 C46.1 C47.1 C48.1 C49.1 C50.1 C51.1 C52.1 C53.1 C54.1 C55.1 C56.1 C57.1 C58.1 C59.1 C60.1 C74.1 C85.1 C86.1 C203.1 C204.1 C205.1 C206.1 C322.2 C323.2 C392.1 R245.2 U1.R18(NVCC_DRAM_1) U1.T18(NVCC_DRAM_2) U1.U18(NVCC_DRAM_3) U1.V9(NVCC_DRAM_13) U1.V10(NVCC_DRAM_4) U1.V11(NVCC_DRAM_5) U1.V12(NVCC_DRAM_6) U1.V13(NVCC_DRAM_7) U1.V14(NVCC_DRAM_8) U1.V15(NVCC_DRAM_9) U1.V16(NVCC_DRAM_10) U1.V17(NVCC_DRAM_11) U1.V18(NVCC_DRAM_12) U2.A1(VDDQ1) U2.A8(VDDQ2) U2.B2(VDD1) U2.C1(VDDQ3) U2.C9(VDDQ4) U2.D2(VDDQ5) U2.D9(VDD2) U2.E9(VDDQ6) U2.F1(VDDQ7) U2.G7(VDD3) U2.H2(VDDQ8) U2.H9(VDDQ9) U2.K2(VDD4) U2.K8(VDD5) U2.N1(VDD6) U2.N9(VDD7) U2.R1(VDD8) U2.R9(VDD9) U3.A1(VDDQ1) U3.A8(VDDQ2) U3.B2(VDD1) U3.C1(VDDQ3) U3.C9(VDDQ4) U3.D2(VDDQ5) U3.D9(VDD2) U3.E9(VDDQ6) U3.F1(VDDQ7) U3.G7(VDD3) U3.H2(VDDQ8) U3.H9(VDDQ9) U3.K2(VDD4) U3.K8(VDD5) U3.N1(VDD6) U3.N9(VDD7) U3.R1(VDD8) U3.R9(VDD9) U4.A1(VDDQ1) U4.A8(VDDQ2) U4.B2(VDD1) U4.C1(VDDQ3) U4.C9(VDDQ4) U4.D2(VDDQ5) U4.D9(VDD2) U4.E9(VDDQ6) U4.F1(VDDQ7) U4.G7(VDD3) U4.H2(VDDQ8) U4.H9(VDDQ9) U4.K2(VDD4) U4.K8(VDD5) U4.N1(VDD6) U4.N9(VDD7) U4.R1(VDD8) U4.R9(VDD9) U5.A1(VDDQ1) U5.A8(VDDQ2) U5.B2(VDD1) U5.C1(VDDQ3) U5.C9(VDDQ4) U5.D2(VDDQ5) U5.D9(VDD2) U5.E9(VDDQ6) U5.F1(VDDQ7) U5.G7(VDD3) U5.H2(VDDQ8) U5.H9(VDDQ9) U5.K2(VDD4) U5.K8(VDD5) U5.N1(VDD6) U5.N9(VDD7) U5.R1(VDD8) U5.R9(VDD9)
+DDR_VREF: C3.1 C4.1 C5.1 C6.1 C7.1 C8.1 C9.1 C10.1 C11.1 C392.2 C393.1 R245.1 R274.2 U1.AC2(DRAM_VREF) U2.H1(VREFDQ) U2.M8(VREFCA) U3.H1(VREFDQ) U3.M8(VREFCA) U4.H1(VREFDQ) U4.M8(VREFCA) U5.H1(VREFDQ) U5.M8(VREFCA)
GND: C1.2 C2.2 C3.2 C4.2 C5.2 C6.2 C7.2 C8.2 C9.2 C10.2 C11.2 C12.2 C19.2 C21.2 C22.2 C23.2 C24.2 C25.2 C26.2 C27.2 C28.2 C29.2 C30.2 C31.2 C32.2 C33.2 C34.2 C35.2 C36.2 C37.2 C38.2 C39.2 C40.2 C41.2 C42.2 C43.2 C44.2 C45.2 C46.2 C47.2 C48.2 C49.2 C50.2 C51.2 C52.2 C53.2 C54.2 C55.2 C56.2 C57.2 C58.2 C59.2 C60.2 C203.2 C204.2 C205.2 C229.2 C277.2 C297.2 C305.2 C306.2 C308.2 C317.2 C318.2 C319.2 C320.2 C321.2 C393.2 R4.1 R5.1 R6.1 R7.1 R8.1 R9.1 R10.2 R274.1 R306.1 R307.1 R308.1 R309.1 U2.A9(VSS1) U2.B1(VSSQ1) U2.B3(VSS2) U2.B9(VSSQ2) U2.D1(VSSQ3) U2.D8(VSSQ4) U2.E1(VSS3) U2.E2(VSSQ5) U2.E8(VSSQ6) U2.F9(VSSQ7) U2.G1(VSSQ8) U2.G8(VSS4) U2.G9(VSSQ9) U2.J2(VSS5) U2.J8(VSS6) U2.M1(VSS7) U2.M9(VSS8) U2.P1(VSS9) U2.P9(VSS10) U2.T1(VSS11) U2.T9(VSS12) U3.A9(VSS1) U3.B1(VSSQ1) U3.B3(VSS2) U3.B9(VSSQ2) U3.D1(VSSQ3) U3.D8(VSSQ4) U3.E1(VSS3) U3.E2(VSSQ5) U3.E8(VSSQ6) U3.F9(VSSQ7) U3.G1(VSSQ8) U3.G8(VSS4) U3.G9(VSSQ9) U3.J2(VSS5) U3.J8(VSS6) U3.M1(VSS7) U3.M9(VSS8) U3.P1(VSS9) U3.P9(VSS10) U3.T1(VSS11) U3.T9(VSS12) U4.A9(VSS1) U4.B1(VSSQ1) U4.B3(VSS2) U4.B9(VSSQ2) U4.D1(VSSQ3) U4.D8(VSSQ4) U4.E1(VSS3) U4.E2(VSSQ5) U4.E8(VSSQ6) U4.F9(VSSQ7) U4.G1(VSSQ8) U4.G8(VSS4) U4.G9(VSSQ9) U4.J2(VSS5) U4.J8(VSS6) U4.M1(VSS7) U4.M9(VSS8) U4.P1(VSS9) U4.P9(VSS10) U4.T1(VSS11) U4.T9(VSS12) U5.A9(VSS1) U5.B1(VSSQ1) U5.B3(VSS2) U5.B9(VSSQ2) U5.D1(VSSQ3) U5.D8(VSSQ4) U5.E1(VSS3) U5.E2(VSSQ5) U5.E8(VSSQ6) U5.F9(VSSQ7) U5.G1(VSSQ8) U5.G8(VSS4) U5.G9(VSSQ9) U5.J2(VSS5) U5.J8(VSS6) U5.M1(VSS7) U5.M9(VSS8) U5.P1(VSS9) U5.P9(VSS10) U5.T1(VSS11) U5.T9(VSS12)
DRAM0_ZQ: R4.2 U2.L8(ZQ)
DRAM0_ZQ1: R306.2 U2.L9(NC_L9)
DRAM1_ZQ: R5.2 U3.L8(ZQ)
DRAM1_ZQ1: R307.2 U3.L9(NC_L9)
DRAM2_ZQ: R8.2 U4.L8(ZQ)
DRAM2_ZQ1: R308.2 U4.L9(NC_L9)
DRAM3_ZQ: R9.2 U5.L8(ZQ)
DRAM3_ZQ1: R309.2 U5.L9(NC_L9)
DRAM_A0: R1.1 U1.AC14(DRAM_A0) U2.N3(A0) U3.N3(A0) U4.N3(A0) U5.N3(A0)
DRAM_A1: R3.1 U1.AB14(DRAM_A1) U2.P7(A1) U3.P7(A1) U4.P7(A1) U5.P7(A1)
DRAM_A2: R12.1 U1.AA14(DRAM_A2) U2.P3(A2) U3.P3(A2) U4.P3(A2) U5.P3(A2)
DRAM_A3: R31.1 U1.Y14(DRAM_A3) U2.N2(A3) U3.N2(A3) U4.N2(A3) U5.N2(A3)
DRAM_A4: R38.1 U1.W14(DRAM_A4) U2.P8(A4) U3.P8(A4) U4.P8(A4) U5.P8(A4)
DRAM_A5: R40.1 U1.AE13(DRAM_A5) U2.P2(A5) U3.P2(A5) U4.P2(A5) U5.P2(A5)
DRAM_A6: R44.1 U1.AC13(DRAM_A6) U2.R8(A6) U3.R8(A6) U4.R8(A6) U5.R8(A6)
DRAM_A7: R50.1 U1.Y13(DRAM_A7) U2.R2(A7) U3.R2(A7) U4.R2(A7) U5.R2(A7)
DRAM_A8: R72.1 U1.AB13(DRAM_A8) U2.T8(A8) U3.T8(A8) U4.T8(A8) U5.T8(A8)
DRAM_A9: R79.1 U1.AE12(DRAM_A9) U2.R3(A9) U3.R3(A9) U4.R3(A9) U5.R3(A9)
DRAM_A10: R103.1 U1.AA15(DRAM_A10) U2.L7(A10/AP) U3.L7(A10/AP) U4.L7(A10/AP) U5.L7(A10/AP)
DRAM_A11: R105.1 U1.AC12(DRAM_A11) U2.R7(A11) U3.R7(A11) U4.R7(A11) U5.R7(A11)
DRAM_A12: R106.1 U1.AD12(DRAM_A12) U2.N7(A12/~{BC}) U3.N7(A12/~{BC}) U4.N7(A12/~{BC}) U5.N7(A12/~{BC})
DRAM_A13: R107.1 U1.AC17(DRAM_A13) U2.T3(A13) U3.T3(A13) U4.T3(A13) U5.T3(A13)
DRAM_A14: R108.1 U1.AA12(DRAM_A14) U2.T7(A14) U3.T7(A14) U4.T7(A14) U5.T7(A14)
DRAM_A15: R111.1 U1.Y12(DRAM_A15) U2.M7(NC_M7) U3.M7(NC_M7) U4.M7(NC_M7) U5.M7(NC_M7)
DRAM_CAS_B: R39.1 U1.AE16(DRAM_CAS) U2.K3(~{CAS}) U3.K3(~{CAS}) U4.K3(~{CAS}) U5.K3(~{CAS})
DRAM_CLK0_N: C327.2 R112.2 U1.AE15(~{DRAM_SDCLK_0}) U2.K7(~{CK}) U3.K7(~{CK}) U4.K7(~{CK}) U5.K7(~{CK})
DRAM_CLK0_P: C327.1 R253.2 U1.AD15(DRAM_SDCLK_0) U2.J7(CK) U3.J7(CK) U4.J7(CK) U5.J7(CK)
DRAM_CLK0_T_CAP: C322.1 R112.1 R253.1
DRAM_CLK1_N: C328.2 R113.2 U1.AE14(~{DRAM_SDCLK_1})
DRAM_CLK1_P: C328.1 R256.2 U1.AD14(DRAM_SDCLK_1)
DRAM_CLK1_T_CAP: C323.1 R113.1 R256.1
DRAM_CS0_B: R66.1 U1.Y16(DRAM_CS0) U2.L2(~{CS}) U3.L2(~{CS}) U4.L2(~{CS}) U5.L2(~{CS})
DRAM_D0: U1.AD2(DRAM_D0) U2.E3(DQ0)
DRAM_D1: U1.AE2(DRAM_D1) U2.H3(DQ4)
DRAM_D2: U1.AC4(DRAM_D2) U2.H7(DQ7)
DRAM_D3: U1.AA5(DRAM_D3) U2.F8(DQ3)
DRAM_D4: U1.AC1(DRAM_D4) U2.F2(DQ2)
DRAM_D5: U1.AD1(DRAM_D5) U2.G2(DQ6)
DRAM_D6: U1.AB4(DRAM_D6) U2.F7(DQ1)
DRAM_D7: U1.AE4(DRAM_D7) U2.H8(DQ5)
DRAM_D8: U1.AD5(DRAM_D8) U2.D7(DQ8)
DRAM_D9: U1.AE5(DRAM_D9) U2.C3(DQ9)
DRAM_D10: U1.AA6(DRAM_D10) U2.B8(DQ14)
DRAM_D11: U1.AE7(DRAM_D11) U2.C8(DQ10)
DRAM_D12: U1.AB5(DRAM_D12) U2.C2(DQ11)
DRAM_D13: U1.AC5(DRAM_D13) U2.A3(DQ15)
DRAM_D14: U1.AB6(DRAM_D14) U2.A2(DQ13)
DRAM_D15: U1.AC7(DRAM_D15) U2.A7(DQ12)
DRAM_D16: U1.AB7(DRAM_D16) U3.E3(DQ0)
DRAM_D17: U1.AA8(DRAM_D17) U3.F7(DQ1)
DRAM_D18: U1.AB9(DRAM_D18) U3.H3(DQ4)
DRAM_D19: U1.Y9(DRAM_D19) U3.H8(DQ5)
DRAM_D20: U1.Y7(DRAM_D20) U3.G2(DQ6)
DRAM_D21: U1.Y8(DRAM_D21) U3.F8(DQ3)
DRAM_D22: U1.AC8(DRAM_D22) U3.F2(DQ2)
DRAM_D23: U1.AA9(DRAM_D23) U3.H7(DQ7)
DRAM_D24: U1.AE9(DRAM_D24) U3.D7(DQ8)
DRAM_D25: U1.Y10(DRAM_D25) U3.A2(DQ13)
DRAM_D26: U1.AE11(DRAM_D26) U3.B8(DQ14)
DRAM_D27: U1.AB11(DRAM_D27) U3.C2(DQ11)
DRAM_D28: U1.AC9(DRAM_D28) U3.C3(DQ9)
DRAM_D29: U1.AD9(DRAM_D29) U3.A7(DQ12)
DRAM_D30: U1.AD11(DRAM_D30) U3.C8(DQ10)
DRAM_D31: U1.AC11(DRAM_D31) U3.A3(DQ15)
DRAM_D32: U1.AA17(DRAM_D32) U4.E3(DQ0)
DRAM_D33: U1.AA18(DRAM_D33) U4.H3(DQ4)
DRAM_D34: U1.AC18(DRAM_D34) U4.F7(DQ1)
DRAM_D35: U1.AE19(DRAM_D35) U4.H7(DQ7)
DRAM_D36: U1.Y17(DRAM_D36) U4.G2(DQ6)
DRAM_D37: U1.Y18(DRAM_D37) U4.F2(DQ2)
DRAM_D38: U1.AB19(DRAM_D38) U4.F8(DQ3)
DRAM_D39: U1.AC19(DRAM_D39) U4.H8(DQ5)
DRAM_D40: U1.Y19(DRAM_D40) U4.D7(DQ8)
DRAM_D41: U1.AB20(DRAM_D41) U4.C2(DQ11)
DRAM_D42: U1.AB21(DRAM_D42) U4.A7(DQ12)
DRAM_D43: U1.AD21(DRAM_D43) U4.C8(DQ10)
DRAM_D44: U1.Y20(DRAM_D44) U4.A2(DQ13)
DRAM_D45: U1.AA20(DRAM_D45) U4.A3(DQ15)
DRAM_D46: U1.AE21(DRAM_D46) U4.B8(DQ14)
DRAM_D47: U1.AC21(DRAM_D47) U4.C3(DQ9)
DRAM_D48: U1.AC22(DRAM_D48) U5.E3(DQ0)
DRAM_D49: U1.AE22(DRAM_D49) U5.G2(DQ6)
DRAM_D50: U1.AE24(DRAM_D50) U5.H7(DQ7)
DRAM_D51: U1.AC24(DRAM_D51) U5.F8(DQ3)
DRAM_D52: U1.AB22(DRAM_D52) U5.F2(DQ2)
DRAM_D53: U1.AC23(DRAM_D53) U5.H3(DQ4)
DRAM_D54: U1.AD25(DRAM_D54) U5.F7(DQ1)
DRAM_D55: U1.AC25(DRAM_D55) U5.H8(DQ5)
DRAM_D56: U1.AB25(DRAM_D56) U5.D7(DQ8)
DRAM_D57: U1.AA21(DRAM_D57) U5.C2(DQ11)
DRAM_D58: U1.Y25(DRAM_D58) U5.B8(DQ14)
DRAM_D59: U1.Y22(DRAM_D59) U5.A2(DQ13)
DRAM_D60: U1.AB23(DRAM_D60) U5.C3(DQ9)
DRAM_D61: U1.AA23(DRAM_D61) U5.A3(DQ15)
DRAM_D62: U1.Y23(DRAM_D62) U5.A7(DQ12)
DRAM_D63: U1.W25(DRAM_D63) U5.C8(DQ10)
DRAM_DQM0: U1.AC3(DRAM_DQM0) U2.E7(LDM)
DRAM_DQM1: U1.AC6(DRAM_DQM1) U2.D3(UDM)
DRAM_DQM2: U1.AB8(DRAM_DQM2) U3.E7(LDM)
DRAM_DQM3: U1.AE10(DRAM_DQM3) U3.D3(UDM)
DRAM_DQM4: U1.AB18(DRAM_DQM4) U4.E7(LDM)
DRAM_DQM5: U1.AC20(DRAM_DQM5) U4.D3(UDM)
DRAM_DQM6: U1.AD24(DRAM_DQM6) U5.E7(LDM)
DRAM_DQM7: U1.Y21(DRAM_DQM7) U5.D3(UDM)
DRAM_DQS0_N: U1.AD3(~{DRAM_SDQS0}) U2.G3(~{LDQS})
DRAM_DQS0_P: U1.AE3(DRAM_SDQS0) U2.F3(LDQS)
DRAM_DQS1_N: U1.AE6(~{DRAM_SDQS1}) U2.B7(~{UDQS})
DRAM_DQS1_P: U1.AD6(DRAM_SDQS1) U2.C7(UDQS)
DRAM_DQS2_N: U1.AE8(~{DRAM_SDQS2}) U3.G3(~{LDQS})
DRAM_DQS2_P: U1.AD8(DRAM_SDQS2) U3.F3(LDQS)
DRAM_DQS3_N: U1.AB10(~{DRAM_SDQS3}) U3.B7(~{UDQS})
DRAM_DQS3_P: U1.AC10(DRAM_SDQS3) U3.C7(UDQS)
DRAM_DQS4_N: U1.AE18(~{DRAM_SDQS4}) U4.G3(~{LDQS})
DRAM_DQS4_P: U1.AD18(DRAM_SDQS4) U4.F3(LDQS)
DRAM_DQS5_N: U1.AE20(~{DRAM_SDQS5}) U4.B7(~{UDQS})
DRAM_DQS5_P: U1.AD20(DRAM_SDQS5) U4.C7(UDQS)
DRAM_DQS6_N: U1.AE23(~{DRAM_SDQS6}) U5.G3(~{LDQS})
DRAM_DQS6_P: U1.AD23(DRAM_SDQS6) U5.F3(LDQS)
DRAM_DQS7_N: U1.AA24(~{DRAM_SDQS7}) U5.B7(~{UDQS})
DRAM_DQS7_P: U1.AA25(DRAM_SDQS7) U5.C7(UDQS)
DRAM_RAS_B: R34.1 U1.AB15(DRAM_RAS) U2.J3(~{RAS}) U3.J3(~{RAS}) U4.J3(~{RAS}) U5.J3(~{RAS})
DRAM_RESET_B: R7.2 U1.Y6(DRAM_RESET) U2.T2(~{RESET}) U3.T2(~{RESET}) U4.T2(~{RESET}) U5.T2(~{RESET})
DRAM_SDBA0: R2.1 U1.AC15(DRAM_SDBA0) U2.M2(BA0) U3.M2(BA0) U4.M2(BA0) U5.M2(BA0)
DRAM_SDBA1: R11.1 U1.Y15(DRAM_SDBA1) U2.N8(BA1) U3.N8(BA1) U4.N8(BA1) U5.N8(BA1)
DRAM_SDBA2: R22.1 U1.AB12(DRAM_SDBA2) U2.M3(BA2) U3.M3(BA2) U4.M3(BA2) U5.M3(BA2)
DRAM_SDCKE0: R6.2 R45.1 U1.Y11(DRAM_SDCKE0) U2.K9(CKE) U3.K9(CKE) U4.K9(CKE) U5.K9(CKE)
DRAM_SDODT0: R77.1 U1.AC16(DRAM_SDODT0) U2.K1(ODT) U3.K1(ODT) U4.K1(ODT) U5.K1(ODT)
DRAM_WE_B: R42.1 U1.AB16(DRAM_SDWE) U2.L3(~{WE}) U3.L3(~{WE}) U4.L3(~{WE}) U5.L3(~{WE})
ZQPAD: R10.1 U1.AE17(ZQPAD)

Not connected (* = marked no-connect by the designer): U1 AA11(DRAM_SDCKE1)* AB17(DRAM_SDODT1)* AD17(DRAM_CS1)*; U2 J1(NC_J1)* J9(NC_J9)* L1(NC_L1)*; U3 J1(NC_J1)* J9(NC_J9)* L1(NC_L1)*; U4 J1(NC_J1)* J9(NC_J9)* L1(NC_L1)*; U5 J1(NC_J1)* J9(NC_J9)* L1(NC_L1)*

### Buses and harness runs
bus DRAM_A[15..0]
bus DRAM_D[63..0]

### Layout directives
net class DRAM_BANK0: DRAM_D0, DRAM_D1, DRAM_D2, DRAM_D3, DRAM_D4, DRAM_D5, DRAM_D6, DRAM_D7, DRAM_DQM0, DRAM_DQS0_N, DRAM_DQS0_P
net class DRAM_BANK1: DRAM_D8, DRAM_D9, DRAM_D10, DRAM_D11, DRAM_D12, DRAM_D13, DRAM_D14, DRAM_D15, DRAM_DQM1, DRAM_DQS1_N, DRAM_DQS1_P
net class DRAM_BANK2: DRAM_D16, DRAM_D17, DRAM_D18, DRAM_D19, DRAM_D20, DRAM_D21, DRAM_D22, DRAM_D23, DRAM_DQM2, DRAM_DQS2_N, DRAM_DQS2_P
net class DRAM_BANK3: DRAM_D24, DRAM_D25, DRAM_D26, DRAM_D27, DRAM_D28, DRAM_D29, DRAM_D30, DRAM_D31, DRAM_DQM3, DRAM_DQS3_N, DRAM_DQS3_P
net class DRAM_BANK4: DRAM_D32, DRAM_D33, DRAM_D34, DRAM_D35, DRAM_D36, DRAM_D37, DRAM_D38, DRAM_D39, DRAM_DQM4, DRAM_DQS4_N, DRAM_DQS4_P
net class DRAM_BANK5: DRAM_D40, DRAM_D41, DRAM_D42, DRAM_D43, DRAM_D44, DRAM_D45, DRAM_D46, DRAM_D47, DRAM_DQM5, DRAM_DQS5_N, DRAM_DQS5_P
net class DRAM_BANK6: DRAM_D48, DRAM_D49, DRAM_D50, DRAM_D51, DRAM_D52, DRAM_D53, DRAM_D54, DRAM_D55, DRAM_DQM6, DRAM_DQS6_N, DRAM_DQS6_P
net class DRAM_BANK7: DRAM_D56, DRAM_D57, DRAM_D58, DRAM_D59, DRAM_D60, DRAM_D61, DRAM_D62, DRAM_D63, DRAM_DQM7, DRAM_DQS7_N, DRAM_DQS7_P
differential pair; net class DIFF100: DRAM_CLK0_N, DRAM_CLK0_P, DRAM_CLK1_N, DRAM_CLK1_P, DRAM_DQS0_N, DRAM_DQS0_P, DRAM_DQS1_N, DRAM_DQS1_P, DRAM_DQS2_N, DRAM_DQS2_P, DRAM_DQS3_N, DRAM_DQS3_P, DRAM_DQS4_N, DRAM_DQS4_P, DRAM_DQS5_N, DRAM_DQS5_P, DRAM_DQS6_N, DRAM_DQS6_P, DRAM_DQS7_N, DRAM_DQS7_P
net class DRAM_ADDR_CTRL: DRAM_A0, DRAM_A1, DRAM_A2, DRAM_A3, DRAM_A4, DRAM_A5, DRAM_A6, DRAM_A7, DRAM_A8, DRAM_A9, DRAM_A10, DRAM_A11, DRAM_A12, DRAM_A13, DRAM_A14, DRAM_A15, DRAM_CAS_B, DRAM_CS0_B, DRAM_RAS_B, DRAM_RESET_B, DRAM_SDBA0, DRAM_SDBA1, DRAM_SDBA2, DRAM_SDCKE0, DRAM_SDODT0, DRAM_WE_B
net class DRAM_SDCLK: DRAM_CLK0_N, DRAM_CLK0_P, DRAM_CLK1_N, DRAM_CLK1_P
net class DRAM_OTHERS: ZQPAD

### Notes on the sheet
- CPU - DDR3, DDR3 MEM
- DESIGN NOTE:
  When using data bit swapping the low order bit of eachbyte must reside at bit 0 of the byte. The remaining 7 data bits can be swapped freely. This restriction is for write leveling calibration. Example D0 to D0 or D0 to D8, and D1-7 can be swapped.
- (near R4) DESIGN NOTE:
  DRAM_SDCKE0 no longer requires external 10 kΩ resistors to GND to minimize current drain during deep sleep mode (DSM).
  We keep the option to stay compatible with old CPU revisions.
- (near U3) DESIGN NOTE:
  DDR VREF voltage is generated by PMIC controller by default. To use resistor divider instead, do not fit R345 and fit R245 & R274.
- DESIGN NOTE:
  Freescale measurement shows maximum current drawn from +1V5_DDR by CPU and memories up to 1400mA.
- Address, command and control signal termination: Place at the end of each signal
- DESIGN NOTE:
  When iMX6 Solo Procesor will be used (32-bit data bus), do not fit U4 and U5.
- DESIGN NOTE:
  8Gb DDR3 memories with second ZQ pad are supported - fit resistors R306-R309.
- DESIGN NOTE:
  Using bit swapping for DATA bus to allow easy pcb routing.
  When swapping the whole bytes, remember to move the DQMx, DQSx, and DQSx_B signals.
- DESIGN NOTE:
  DDR3 termination max. current calculation:
  I_one = Vtt / R_vtt = 0.75 V / 47 Ohm = 16 mA
  I_vtt = I_one * number of res = 16 mA * 25 = 0.4 A
- FREE for personal and commercial use. See the license.
- (near *#11) LAYOUT NOTE:
  Maintain 50 Ohm impedance for single ended tracks.
- Variant:
- Checked by
- Designed by www.fedevel.com

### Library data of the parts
C1-C6 C8-C12 C21-C26 C30 C34-C60 C203-C205 = C0603X5R0J224M030BB: CAP CER 0.22UF 6.3V 20% X5R 0201; Manufacturer: TDK Corporation; Capacitance: 0.22µF; .Checked PCB: MM
C7 C13-C18 C74 C85 C86 C206 C229 C277 C297 C305 C306 C308 C317-C320 C322 C323 = C0603X5R1C104K030BC: CAP CER 0.1UF 16V 10% X5R 0201; Manufacturer: TDK Corporation; Capacitance: 0.1µF; .Creator: MM
C19 = C1608X5R0J106M: CAP CER 10UF 6.3V X5R 20% 0603; Manufacturer: TDK Corporation; Capacitance: 10µF; Value: 10µF; .Checked PCB: used
C20 C27-C29 C31-C33 C321 = GRM188R60G226MEA0L: CAP CER 22UF 4V 20% X5R 0603; Manufacturer: Murata Electronics North America; Capacitance: 22µF; .Checked PCB: used; .Creator: MM
C327 C328 = C0603C0G1H2R2C030BA: CAP CER 2.2PF 50V C0G 0201; Manufacturer: TDK Corporation; Tolerance: ±0.25pF; Temperature Coefficient: C0G, NP0; .Checked PCB: MM
C392 C393 = C1005X5R1H104K: CAP CER .10UF 50V X5R 10% 0402; Manufacturer: TDK Corporation; Capacitance: 0.1µF; Value: 100nF; .Checked PCB: used
R1-R3 R11 R12 R22 R31 R34 R38-R40 R42 R44 R45 R50 R66 R72 R77 R79 R103 R105-R108 R111 = MCR006YRTF47R0: RES SMD 47 OHM 1% 1/20W 0201; Manufacturer: Rohm Semiconductor; Resistance (Ohms): 47; Power (Watts): 0.05W, 1/20W; Temperature Coefficient: ±250ppm/°C; .Creator: MM
R4 R5 R8-R10 R306-R309 = RMCF0201FT240R: RES 240 OHM 1/20W 1% 0201; Manufacturer: Stackpole Electronics Inc; Resistance (Ohms): 240; Power (Watts): 0.05W, 1/20W; Temperature Coefficient: ±200ppm/°C; .Creator: MM
R6 R7 = RC0201FR-0710KL: RES 10K OHM 1/20W 1% 0201 SMD; Manufacturer: Yageo; Power (Watts): 0.05W, 1/20W; Temperature Coefficient: ±200ppm/°C; .Creator: MM
R112 R113 R253 R256 = MCR006YRTF49R9: RES 49.9 OHM 1/20W 1% 0201 SMD; Manufacturer: Rohm Semiconductor; Resistance (Ohms): 49.9; Power (Watts): 0.05W, 1/20W; Temperature Coefficient: ±250ppm/°C; .Creator: MM
R245 R274 = RMCF0402FT240R: RES TF 240 OHM 1% 0.0625W 0402; Manufacturer: Stackpole Electronics Inc; Resistance (Ohms): 240; Power (Watts): 0.063W, 1/16W; .Checked PCB: used; Temperature Coefficient: ±100ppm/°C
U1 = MCIMX6Q5EYM10AC_v.ORX: as U1 on sheet [10] - CPU - GPIO, PWM, LEDS, BUTTONS
U2-U5 = MT41J256M16HA-125:E: IC DDR3 SDRAM 4GBIT 800MHZ FBGA; Manufacturer: Micron Technology Inc; Format - Memory: RAM; Memory Size: 4G (256M x 16); Interface: Parallel; Voltage - Supply: 1.425 V ~ 1.575 V; .Creator: MM

## Sheet [11] - CPU - JTAG, CONTROL.SchDoc
size A2; DocumentNumber: 11; SheetNumber: 11; SheetTotal: 31
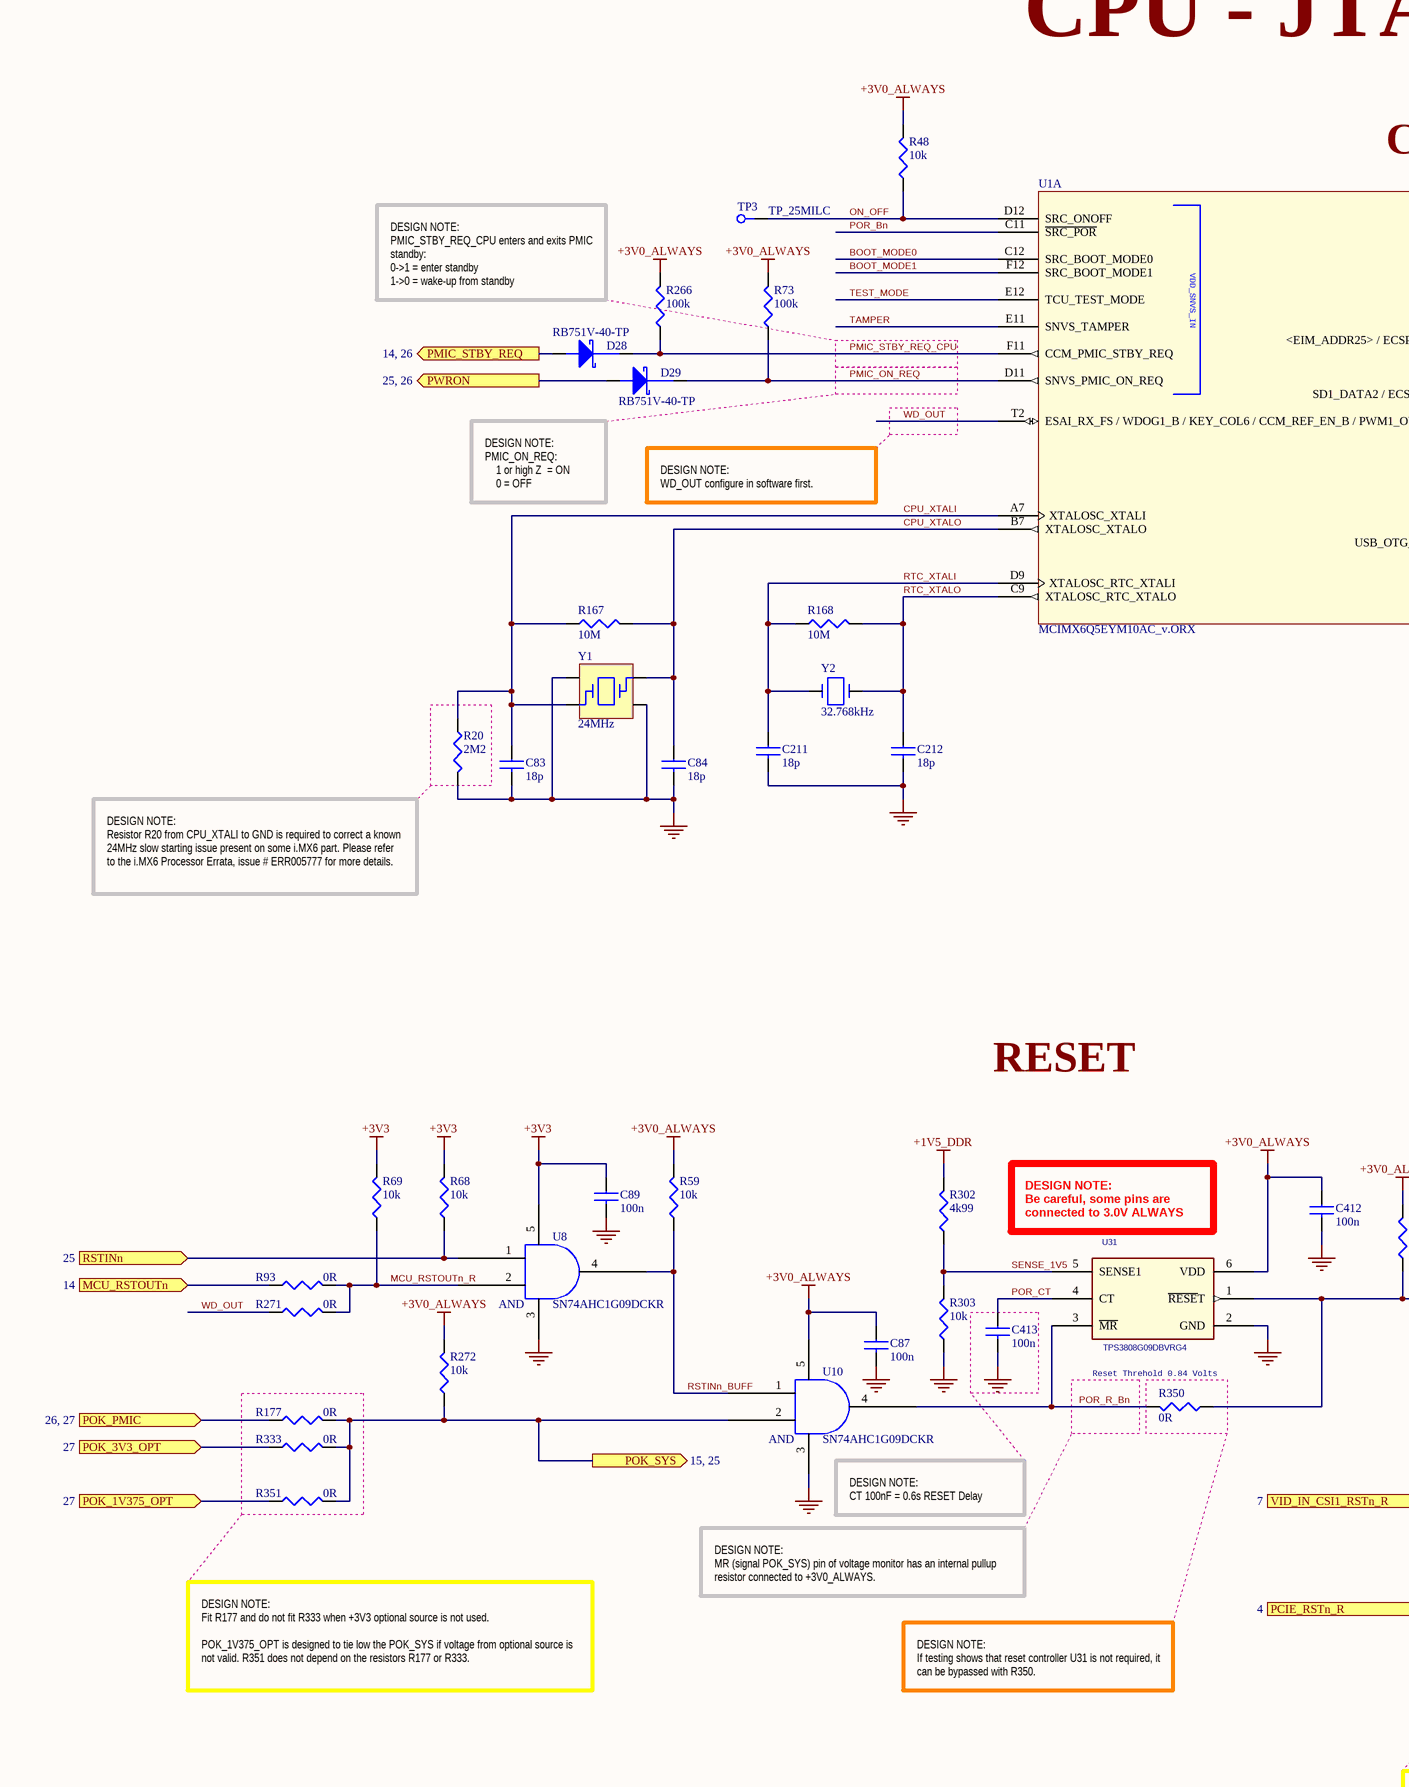
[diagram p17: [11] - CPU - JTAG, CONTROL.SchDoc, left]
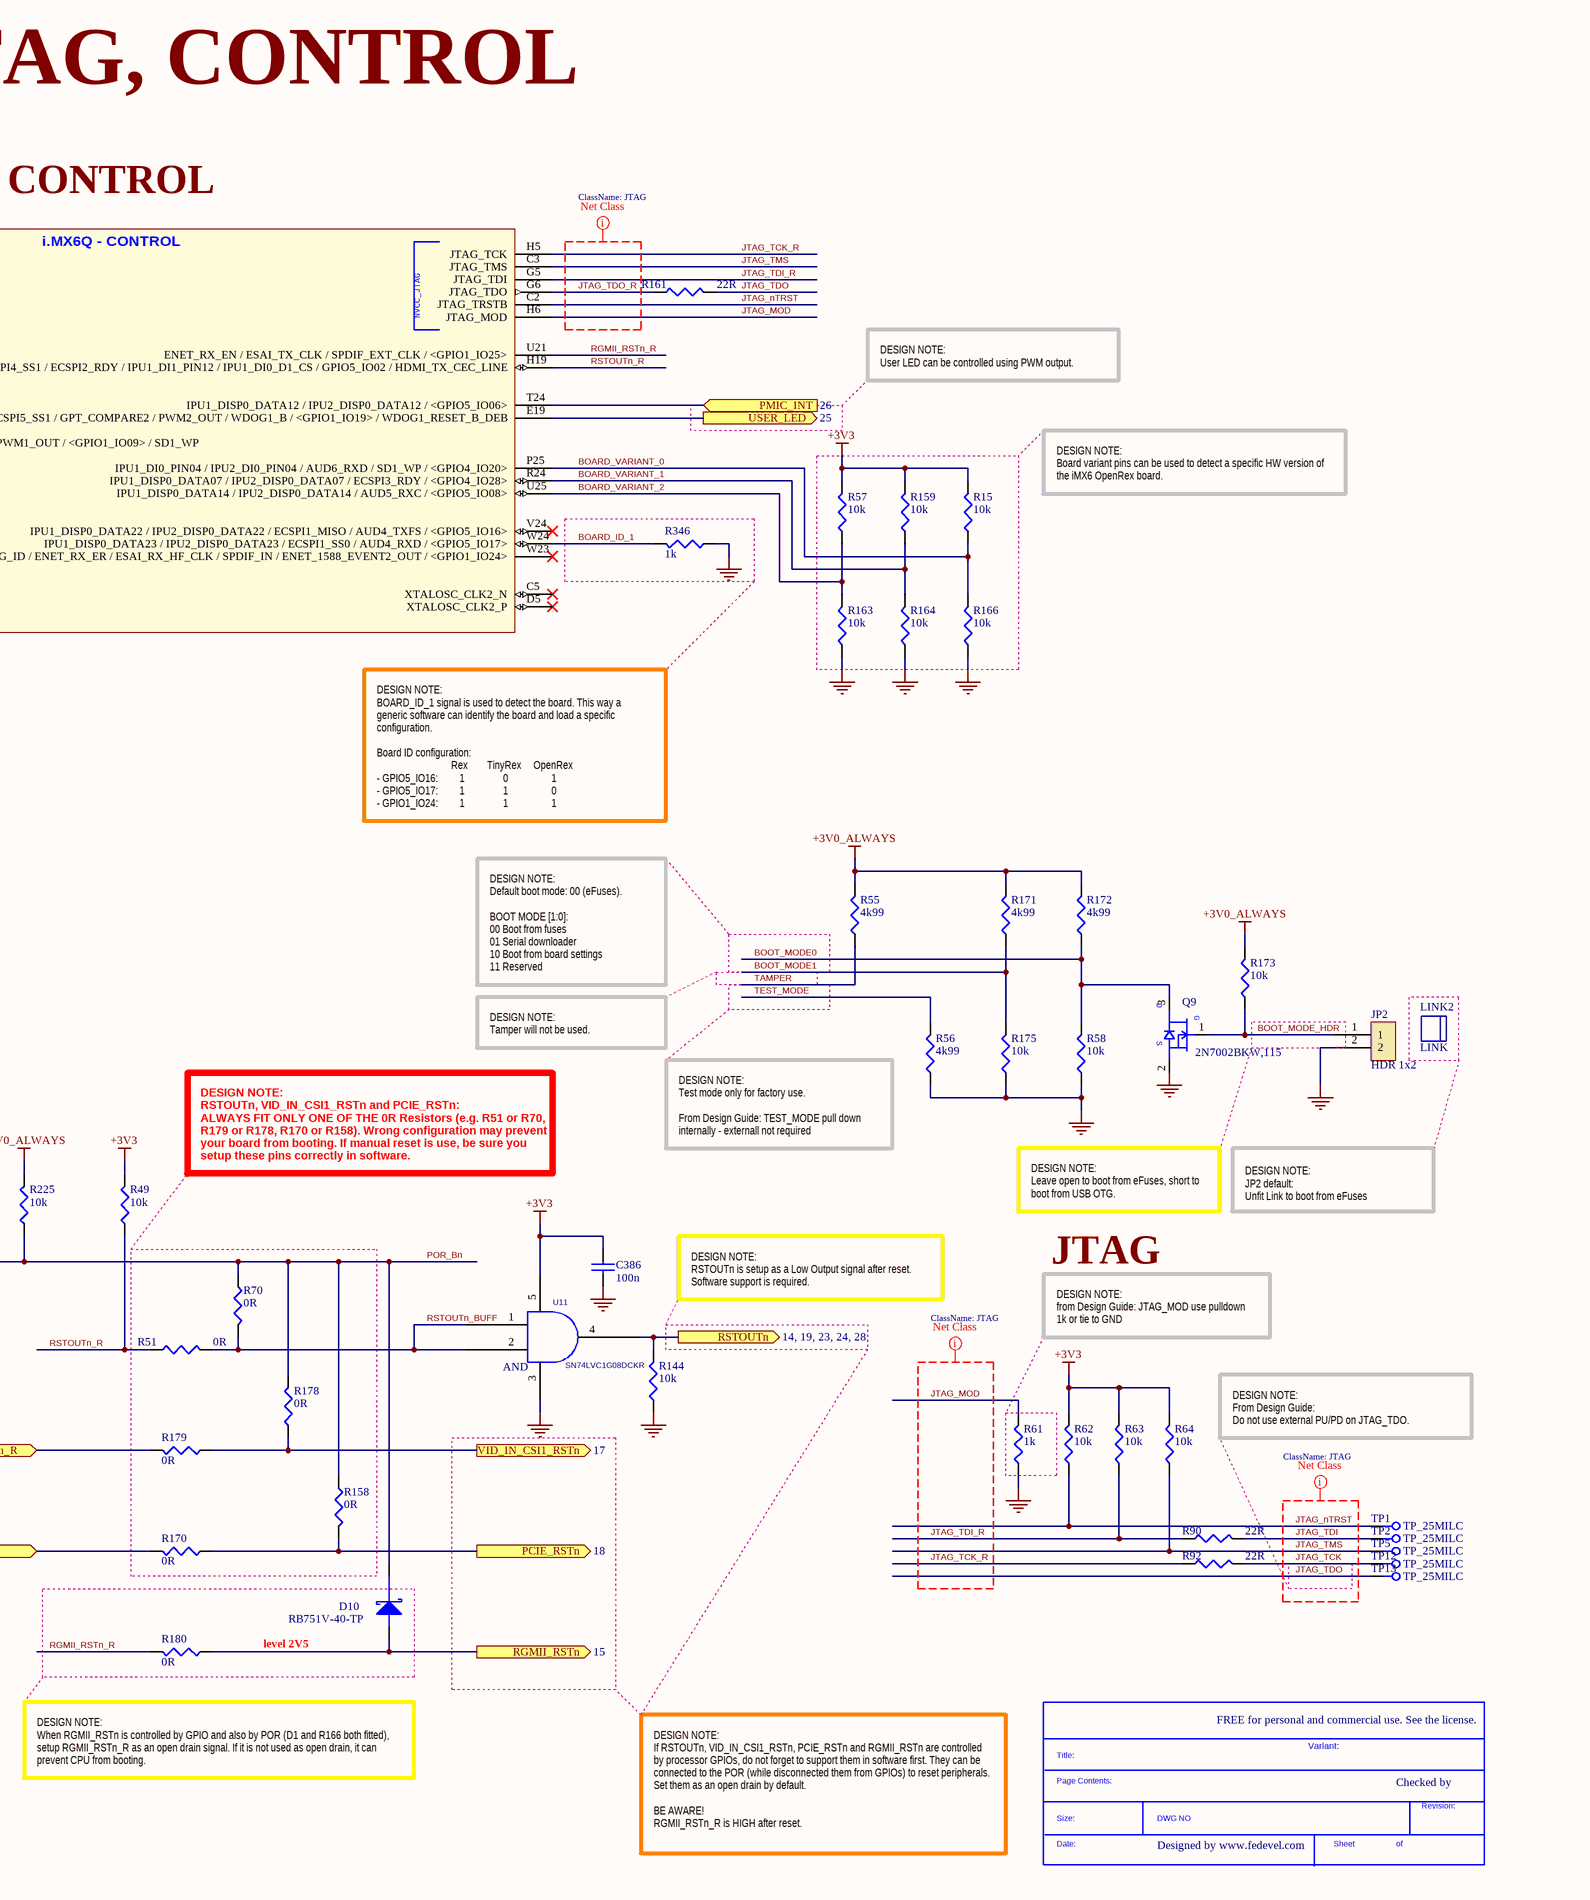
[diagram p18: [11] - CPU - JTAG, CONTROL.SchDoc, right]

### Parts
(Parts that share a designator on the sheet are numbered #1, #2 ... from top to bottom, then left to right.)
*#12  SDTitleBlock  (value not drawn)  (graphical)
C83  18p  [C0402]
C84  18p  [C0402]
C87  100n  [C0402]
C89  100n  [C0402]
C211  18p  [C0201]
C212  18p  [C0201]
C386  100n  [C0402]
C412  100n  [C0402]
C413  100n  [C0402]
D10  RB751V-40-TP  [SOD323]
D28  RB751V-40-TP  [SOD323]
D29  RB751V-40-TP  [SOD323]
JP2  HDR 1x2  [HDR_1x2_2.54MM]
LINK2  LINK  (mechanical)
Q9  2N7002BKW,115  [SC70_SOT323]
R15  10k  [R0402]
R20  2M2  [R0402]
R48  10k  [R0402]
R49  10k  [R0402]
R51  0R  [R0402]
R55  4k99  [R0201]
R56  4k99  [R0201]
R57  10k  [R0402]
R58  10k  [R0402]
R59  10k  [R0402]
R61  1k  [R0201]
R62  10k  [R0402]
R63  10k  [R0402]
R64  10k  [R0402]
R68  10k  [R0402]
R69  10k  [R0402]
R70  0R  [R0402]
R73  100k  [R0402]
R90  22R  [R0402]
R92  22R  [R0402]
R93  0R  [R0402]
R144  10k  [R0402]
R158  0R  [R0402]
R159  10k  [R0402]
R161  22R  [R0402]
R163  10k  [R0402]
R164  10k  [R0402]
R166  10k  [R0402]
R167  10M  [R0402]
R168  10M  [R0201]
R170  0R  [R0402]
R171  4k99  [R0402]
R172  4k99  [R0402]
R173  10k  [R0402]
R175  10k  [R0402]
R177  0R  [R0402]
R178  0R  [R0402]
R179  0R  [R0402]
R180  0R  [R0402]
R225  10k  [R0402]
R266  100k  [R0402]
R271  0R  [R0402]
R272  10k  [R0402]
R302  4k99  [R0402]
R303  10k  [R0402]
R333  0R  [R0402]
R346  1k  [R0402]
R350  0R  [R0402]
R351  0R  [R0402]
TP1  TP_25MILC  [TP_25C]  (no BOM)
TP2  TP_25MILC  [TP_25C]  (no BOM)
TP3  TP_25MILC  [TP_25C]  (no BOM)
TP5  TP_25MILC  [TP_25C]  (no BOM)
TP12  TP_25MILC  [TP_25C]  (no BOM)
TP13  TP_25MILC  [TP_25C]  (no BOM)
U1  MCIMX6Q5EYM10AC_v.ORX  [PBGA624]  (part A of 21)
U8  SN74AHC1G09DCKR  [SC70_5]
U10  SN74AHC1G09DCKR  [SC70_5]
U11  SN74LVC1G08DCKR  [SC70_5]
U31  TPS3808G09DBVRG4  [DBV_SOT_23_6]
Y1  24MHz  [ABM8]
Y2  32.768kHz  [ABS06]

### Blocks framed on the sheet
level 2V5: D10 R180

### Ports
MCU_RSTOUTn (in, see 14), PCIE_RSTn (out, see 18), PCIE_RSTn_R (in, see 4), PMIC_INT (in, see 26), PMIC_STBY_REQ (out, see 14, 26), POK_1V375_OPT (in, see 27), POK_3V3_OPT (in, see 27), POK_PMIC (see 26, 27), POK_SYS (see 15, 25), PWRON (out, see 25, 26), RGMII_RSTn (out, see 15), RSTINn (in, see 25), RSTOUTn (see 14, 19, 23, 24, 28), USER_LED (out, see 25), VID_IN_CSI1_RSTn (out, see 17), VID_IN_CSI1_RSTn_R (in, see 7)

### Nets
+1V5_DDR: R302.2
+3V0_ALWAYS: C87.1 C412.1 R48.2 R55.2 R59.2 R73.2 R171.2 R172.2 R173.2 R225.2 R266.2 R272.2 U10.5(VCC) U31.6(VDD)
+3V3: C89.1 C386.1 R15.2 R49.2 R57.2 R62.2 R63.2 R64.2 R68.2 R69.2 R159.2 U8.5(VCC) U11.5(VCC)
GND: C83.2 C84.2 C87.2 C89.2 C211.2 C212.2 C386.2 C412.2 C413.2 JP2.2 Q9.2(SOURCE) R20.2 R56.1 R58.1 R61.1 R144.1 R163.1 R164.1 R166.1 R175.1 R303.1 R346.1 U8.3(GND) U10.3(GND) U11.3(GND) U31.2(GND) Y1.2 Y1.4
BOARD_ID_1: R346.2 U1.W24(IPU1_DISP0_DATA23_/_IPU2_DISP0_DATA23_/_ECSPI1_SS0_/_AUD4_RXD_/_<GPIO5_IO17>)
BOARD_VARIANT_0: R15.1 R166.2 U1.P25(IPU1_DI0_PIN04_/_IPU2_DI0_PIN04_/_AUD6_RXD_/_SD1_WP_/_<GPIO4_IO20>)
BOARD_VARIANT_1: R159.1 R164.2 U1.R24(IPU1_DISP0_DATA07_/_IPU2_DISP0_DATA07_/_ECSPI3_RDY_/_<GPIO4_IO28>)
BOARD_VARIANT_2: R57.1 R163.2 U1.U25(IPU1_DISP0_DATA14_/_IPU2_DISP0_DATA14_/_AUD5_RXC_/_<GPIO5_IO08>)
BOOT_MODE0: Q9.3(DRAIN) R58.2 R172.1 U1.C12(SRC_BOOT_MODE0)
BOOT_MODE1: R171.1 R175.2 U1.F12(SRC_BOOT_MODE1)
BOOT_MODE_HDR: JP2.1 Q9.1(GATE) R173.1
CPU_XTALI: C83.1 R20.1 R167.1 U1.A7(XTALOSC_XTALI) Y1.3
CPU_XTALO: C84.1 R167.2 U1.B7(XTALOSC_XTALO) Y1.1
JTAG_MOD: R61.2 U1.H6(JTAG_MOD)
JTAG_nTRST: R62.1 TP1.1 U1.C2(JTAG_TRSTB)
JTAG_TCK: R92.2 TP12.1
JTAG_TCK_R: R92.1 U1.H5(JTAG_TCK)
JTAG_TDI: R90.2 TP2.1
JTAG_TDI_R: R63.1 R90.1 U1.G5(JTAG_TDI)
JTAG_TDO: R161.2 TP13.1
JTAG_TDO_R: R161.1 U1.G6(JTAG_TDO)
JTAG_TMS: R64.1 TP5.1 U1.C3(JTAG_TMS)
MCU_RSTOUTn: R93.1 ; port MCU_RSTOUTn
MCU_RSTOUTn_R: R69.1 R93.2 R271.2 U8.2(B)
ON_OFF: R48.1 TP3.1 U1.D12(SRC_ONOFF)
PCIE_RSTn: R158.2 R170.1 ; port PCIE_RSTn
PCIE_RSTn_R: R170.2 ; port PCIE_RSTn_R
PMIC_INT: U1.T24(IPU1_DISP0_DATA12_/_IPU2_DISP0_DATA12_/_<GPIO5_IO06>) ; port PMIC_INT
PMIC_ON_REQ: D29.1(cathode) R73.1 U1.D11(SNVS_PMIC_ON_REQ)
PMIC_STBY_REQ: D28.2(ANODE) ; port PMIC_STBY_REQ
PMIC_STBY_REQ_CPU: D28.1(cathode) R266.1 U1.F11(CCM_PMIC_STBY_REQ)
POK_1V375_OPT: R351.1 ; port POK_1V375_OPT
POK_3V3_OPT: R333.1 ; port POK_3V3_OPT
POK_PMIC: R177.1 ; port POK_PMIC
POK_SYS: R177.2 R272.1 R333.2 R351.2 U10.2(B) ; port POK_SYS
POR_Bn: D10.1(cathode) R70.1 R158.1 R178.2 R225.1 R350.1 U1.C11(~{SRC_POR}) U31.1(~{RESE}T)
POR_CT: C413.1 U31.4(CT)
POR_R_Bn: R350.2 U10.4(Y) U31.3(~{MR})
PWRON: D29.2(ANODE) ; port PWRON
RGMII_RSTn: D10.2(ANODE) R180.1 ; port RGMII_RSTn
RGMII_RSTn_R: R180.2 U1.U21(ENET_RX_EN_/_ESAI_TX_CLK_/_SPDIF_EXT_CLK_/_<GPIO1_IO25>)
RSTINn: R68.1 U8.1(A) ; port RSTINn
RSTINn_BUFF: R59.1 U8.4(Y) U10.1(A)
RSTOUTn: R144.2 U11.4(Y) ; port RSTOUTn
RSTOUTn_BUFF: R51.2 R70.2 U11.1(A) U11.2(B)
RSTOUTn_R: R49.1 R51.1 U1.H19(<EIM_ADDR25>_/_ECSPI4_SS1_/_ECSPI2_RDY_/_IPU1_DI1_PIN12_/_IPU1_DI0_D1_CS_/_GPIO5_IO02_/_HDMI_TX_CEC_LINE)
RTC_XTALI: C211.1 R168.1 U1.D9(XTALOSC_RTC_XTALI) Y2.1
RTC_XTALO: C212.1 R168.2 U1.C9(XTALOSC_RTC_XTALO) Y2.2
SENSE_1V5: R302.1 R303.2 U31.5(SENSE1)
TAMPER: R55.1 U1.E11(SNVS_TAMPER)
TEST_MODE: R56.2 U1.E12(TCU_TEST_MODE)
USER_LED: U1.E19(SD1_DATA2_/_ECSPI5_SS1_/_GPT_COMPARE2_/_PWM2_OUT_/_WDOG1_B_/_<GPIO1_IO19>_/_WDOG1_RESET_B_DEB) ; port USER_LED
VID_IN_CSI1_RSTn: R178.1 R179.1 ; port VID_IN_CSI1_RSTn
VID_IN_CSI1_RSTn_R: R179.2 ; port VID_IN_CSI1_RSTn_R
WD_OUT: R271.1 U1.T2(ESAI_RX_FS_/_WDOG1_B_/_KEY_COL6_/_CCM_REF_EN_B_/_PWM1_OUT_/_<GPIO1_IO09>_/_SD1_WP)

Not connected (* = marked no-connect by the designer): U1 C5(XTALOSC_CLK2_N)* D5(XTALOSC_CLK2_P)* V24(IPU1_DISP0_DATA22_/_IPU2_DISP0_DATA22_/_ECSPI1_MISO_/_AUD4_TXFS_/_<GPIO5_IO16>)* W23(USB_OTG_ID_/_ENET_RX_ER_/_ESAI_RX_HF_CLK_/_SPDIF_IN_/_ENET_1588_EVENT2_OUT_/_<GPIO1_IO24>)*

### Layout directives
net class JTAG: JTAG_MOD, JTAG_nTRST, JTAG_TCK, JTAG_TCK_R, JTAG_TDI, JTAG_TDI_R, JTAG_TDO, JTAG_TDO_R, JTAG_TMS

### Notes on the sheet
- CPU - JTAG, CONTROL
- CONTROL
- DESIGN NOTE:
  PMIC_STBY_REQ_CPU enters and exits PMIC standby:
  0->1 = enter standby
  1->0 = wake-up from standby
- DESIGN NOTE:
  User LED can be controlled using PWM output.
- DESIGN NOTE:
  PMIC_ON_REQ:
  1 or high Z  = ON
  0 = OFF
- DESIGN NOTE:
  WD_OUT configure in software first.
- DESIGN NOTE:
  Board variant pins can be used to detect a specific HW version of the iMX6 OpenRex board.
- DESIGN NOTE:
  BOARD_ID_1 signal is used to detect the board. This way a generic software can identify the board and load a specific configuration.
  Board ID configuration:
  Rex        TinyRex     OpenRex
  - GPIO5_IO16:         1                0                  1
  - GPIO5_IO17:         1                1                  0
  - GPIO1_IO24:         1                1                  1
- DESIGN NOTE:
  Resistor R20 from CPU_XTALI to GND is required to correct a known 24MHz slow starting issue present on some i.MX6 part. Please refer to the i.MX6 Processor Errata, issue # ERR005777 for more details.
- DESIGN NOTE:
  Default boot mode: 00 (eFuses).
  BOOT MODE [1:0]:
  00 Boot from fuses
  01 Serial downloader
  10 Boot from board settings
  11 Reserved
- DESIGN NOTE:
  Tamper will not be used.
- RESET
- DESIGN NOTE:
  RSTOUTn, VID_IN_CSI1_RSTn and PCIE_RSTn:
  ALWAYS FIT ONLY ONE OF THE 0R Resistors (e.g. R51 or R70, R179 or R178, R170 or R158). Wrong configuration may prevent your board from booting. If manual reset is use, be sure you setup these pins correctly in software.
- DESIGN NOTE:
  Test mode only for factory use.
  From Design Guide: TEST_MODE pull down internally - externall not required
- (near U31) DESIGN NOTE:
  Be careful, some pins are connected to 3.0V ALWAYS
- DESIGN NOTE:
  Leave open to boot from eFuses, short to boot from USB OTG.
- DESIGN NOTE:
  JP2 default:
  Unfit Link to boot from eFuses
- DESIGN NOTE:
  RSTOUTn is setup as a Low Output signal after reset. Software support is required.
- JTAG
- Reset Threhold 0.84 Volts
- DESIGN NOTE:
  from Design Guide: JTAG_MOD use pulldown 1k or tie to GND
- (near U10) DESIGN NOTE:
  CT 100nF = 0.6s RESET Delay
- DESIGN NOTE:
  From Design Guide:
  Do not use external PU/PD on JTAG_TDO.
- DESIGN NOTE:
  MR (signal POK_SYS) pin of voltage monitor has an internal pullup resistor connected to +3V0_ALWAYS.
- DESIGN NOTE:
  Fit R177 and do not fit R333 when +3V3 optional source is not used.
  POK_1V375_OPT is designed to tie low the POK_SYS if voltage from optional source is not valid. R351 does not depend on the resistors R177 or R333.
- DESIGN NOTE:
  If testing shows that reset controller U31 is not required, it can be bypassed with R350.
- FREE for personal and commercial use. See the license.
- DESIGN NOTE:
  When RGMII_RSTn is controlled by GPIO and also by POR (D1 and R166 both fitted), setup RGMII_RSTn_R as an open drain signal. If it is not used as open drain, it can prevent CPU from booting.
- Variant:
- Checked by
- (near *#12) DESIGN NOTE:
  If RSTOUTn, VID_IN_CSI1_RSTn, PCIE_RSTn and RGMII_RSTn are controlled by processor GPIOs, do not forget to support them in software first. They can be connected to the POR (while disconnected them from GPIOs) to reset peripherals. Set them as an open drain by default.
  BE AWARE!
  RGMII_RSTn_R is HIGH after reset.
- Designed by www.fedevel.com

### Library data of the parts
C83 C84 = C1005C0G1H180J: CAP CER 18PF 50V C0G 5% 0402; Manufacturer: TDK Corporation; .Checked PCB: used; Temperature Coefficient: C0G, NP0
C87 C89 C386 C412 C413 = C1005X5R1H104K: as C392 on sheet [03] - CPU - DDR3, DDR3 MEM
C211 C212 = C0603C0G1H180J030BA: CAP CER 18PF 50V 5% C0G 0201; Manufacturer: TDK Corporation; Temperature Coefficient: C0G, NP0; .Creator: MM
D10 D28 D29 = RB751V-40-TP: DIODE SCHTKY 30MA 30V SOD-323; Manufacturer: Micro Commercial Co; Diode Type: Schottky; Voltage - Forward (Vf) (Max) @ If: 370mV @ 1mA; Speed: Small Signal =< 200mA (Io), Any Speed; Current - Reverse Leakage @ Vr: 500nA @ 30V; Capacitance @ Vr, F: 2pF @ 1V, 1MHz; .Checked PCB: used
JP2 = 68001-202HLF: BERGSTIK II .100" SR STRAIGHT; Manufacturer: FCI; Connector Type: Header, Unshrouded; Number of Positions: 2; Number of Positions Loaded: All; Pitch: 0.100" (2.54mm); .Checked PCB: used
LINK2 = QPC02SXGN-RC: CONN JUMPER SHORTING .100" GOLD; Manufacturer: Sullins Connector Solutions; Gender: Female Sockets; Number of Positions or Pins (Grid): 2 (1 x 2); Pitch: 0.100" (2.54mm); .Checked SCH: used
Q9 = 2N7002BKW,115: MOSFET N-CH 60V 310MA SOT323; Manufacturer: NXP Semiconductors; FET Type: MOSFET N-Channel, Metal Oxide; FET Feature: Logic Level Gate; Rds On (Max) @ Id, Vgs: 1.6 Ohm @ 500mA, 10V; Vgs(th) (Max) @ Id: 2.1V @ 250µA; Gate Charge (Qg) @ Vgs: 0.6nC @ 4.5V; Input Capacitance (Ciss) @ Vds: 50pF @ 10V; Power - Max: 275mW; .Checked PCB: used
R15 R48 R49 R57-R59 R62-R64 R68 R69 R144 R159 R163 R164 R166 R173 R175 R225 R272 R303 = RC0402FR-0710KL: as R212 on sheet [10] - CPU - GPIO, PWM, LEDS, BUTTONS
R20 = CRCW04022M20FKED: RES 2.20M OHM 1/16W 1% 0402 SMD; Manufacturer: Vishay Dale; Resistance (Ohms): 2.2M; Power (Watts): 0.063W, 1/16W; Temperature Coefficient: ±100ppm/°C; .Creator: MM; .Checked PCB: used
R51 R70 R93 R158 R170 R177-R180 R271 R333 R350 R351 = RC0402JR-070RL: RES 0.0 OHM 1/16W 0402 SMD; Manufacturer: Yageo; Resistance (Ohms): 0.0; Power (Watts): 0.063W, 1/16W; Tolerance: Jumper; .Checked PCB: used
R55 R56 = RMCF0201FT4K99: RES 4.99K OHM 1/20W 1% 0201; Manufacturer: Stackpole Electronics Inc; Power (Watts): 0.05W, 1/20W; Temperature Coefficient: ±200ppm/°C; .Creator: MM
R61 = RC0201FR-071KL: RES 1K OHM 1/20W 1% 0201 SMD; Manufacturer: Yageo; Power (Watts): 0.05W, 1/20W; Temperature Coefficient: ±200ppm/°C; .Creator: MM
R73 R266 = RMCF0402FT100K: RES 100K OHM 1/16W 1% 0402 SMD; Manufacturer: Stackpole Electronics Inc; Power (Watts): 0.063W, 1/16W; .Checked PCB: used; Temperature Coefficient: ±100ppm/°C
R90 R92 R161 = RC0402FR-0722RL: as R124 on sheet [09] - CPU - SD, AUDIO, I2C, CAN
R167 = CRCW040210M0FKED: RES 10.0M OHM 1/16W 1% 0402 SMD; Manufacturer: Vishay Dale; Power (Watts): 0.063W, 1/16W; Temperature Coefficient: ±100ppm/°C; .Checked PCB: RF
R168 = MCR006YZPF1005: RES 10M OHM 1/20W 1% 0201 SMD; Manufacturer: Rohm Semiconductor; Power (Watts): 0.05W, 1/20W; Temperature Coefficient: ±250ppm/°C; .Creator: MM
R171 R172 R302 = RMCF0402FT4K99: as R257 on sheet [10] - CPU - GPIO, PWM, LEDS, BUTTONS
R346 = RC0402FR-071KL: RES 1.00K OHM 1/16W 1% 0402 SMD; Manufacturer: Yageo; Power (Watts): 0.063W, 1/16W; .Checked PCB: used; Temperature Coefficient: ±100ppm/°C
TP1-TP3 TP5 TP12 TP13 = TP_25MILC: Test Point 25mil
U1 = MCIMX6Q5EYM10AC_v.ORX: as U1 on sheet [10] - CPU - GPIO, PWM, LEDS, BUTTONS
U8 U10 = SN74AHC1G09DCKR: IC GATE AND 1CH 2-INP SC-70-5; Manufacturer: Texas Instruments; Logic Type: AND Gate; Number of Circuits: 1; Number of Inputs: 2; Voltage - Supply: 2 V ~ 5.5 V; Current - Quiescent (Max): 1µA; Current - Output High, Low: -, 8mA; Logic Level - Low: 0.5 V ~ 1.65 V; Logic Level - High: 1.5 V ~ 3.85 V; Max Propagation Delay @ V, Max CL: 7.5ns @ 5V, 50pF; .Creator: MM; .Checked PCB: RF, used by MM
U11 = SN74LVC1G08DCKR: SINGLE POSITIVE AND GATE SC-70; Manufacturer: Texas Instruments; .Checked PCB: used; Number of Inputs: 2; Voltage - Supply: 1.65 V ~ 5.5 V; Number of Circuits: 1; Current - Output High, Low: 32mA, 32mA
U31 = TPS3808G09DBVR: IC VOLT SUPERVISOR 0.9V SOT23-6; Part #: 102020-0009R; Manufacturer: Texas Instruments; .Checked PCB: used; Number of Voltages Monitored: 1; Output: Open Drain or Open Collector; Reset: Active Low; Reset Timeout: Adjustable/Selectable; Voltage - Threshold: 0.84V
Y1 = ABM8-24.000MHZ-R60-D-1-W-T: CRYSTAL 24MHZ 18PF SMD; Manufacturer: Abracon Corporation; Frequency Stability: ±25ppm; Frequency Tolerance: ±10ppm; ESR (Equivalent Series Resistance): 50 Ohm; Operating Mode: Fundamental; .Creator: MM
Y2 = ABS06-32.768KHZ-9-1-T: CRYSTAL 32.768 KHZ 9.0 PF SMD; Manufacturer: Abracon Corporation; .Checked PCB: used; Frequency Stability: ±10ppm; Load Capacitance: 9pF; Operating Mode: Fundamental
